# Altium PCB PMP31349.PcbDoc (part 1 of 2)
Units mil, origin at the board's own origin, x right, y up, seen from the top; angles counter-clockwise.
Board outline 2490.35 x 2400.55 mil, 4 copper layers (Top Layer, Internal Layer 1, Internal Layer 2, Bottom Layer), stack 73.068 mil thick; 110 components, 35 nets, 244 pads, 375 vias.
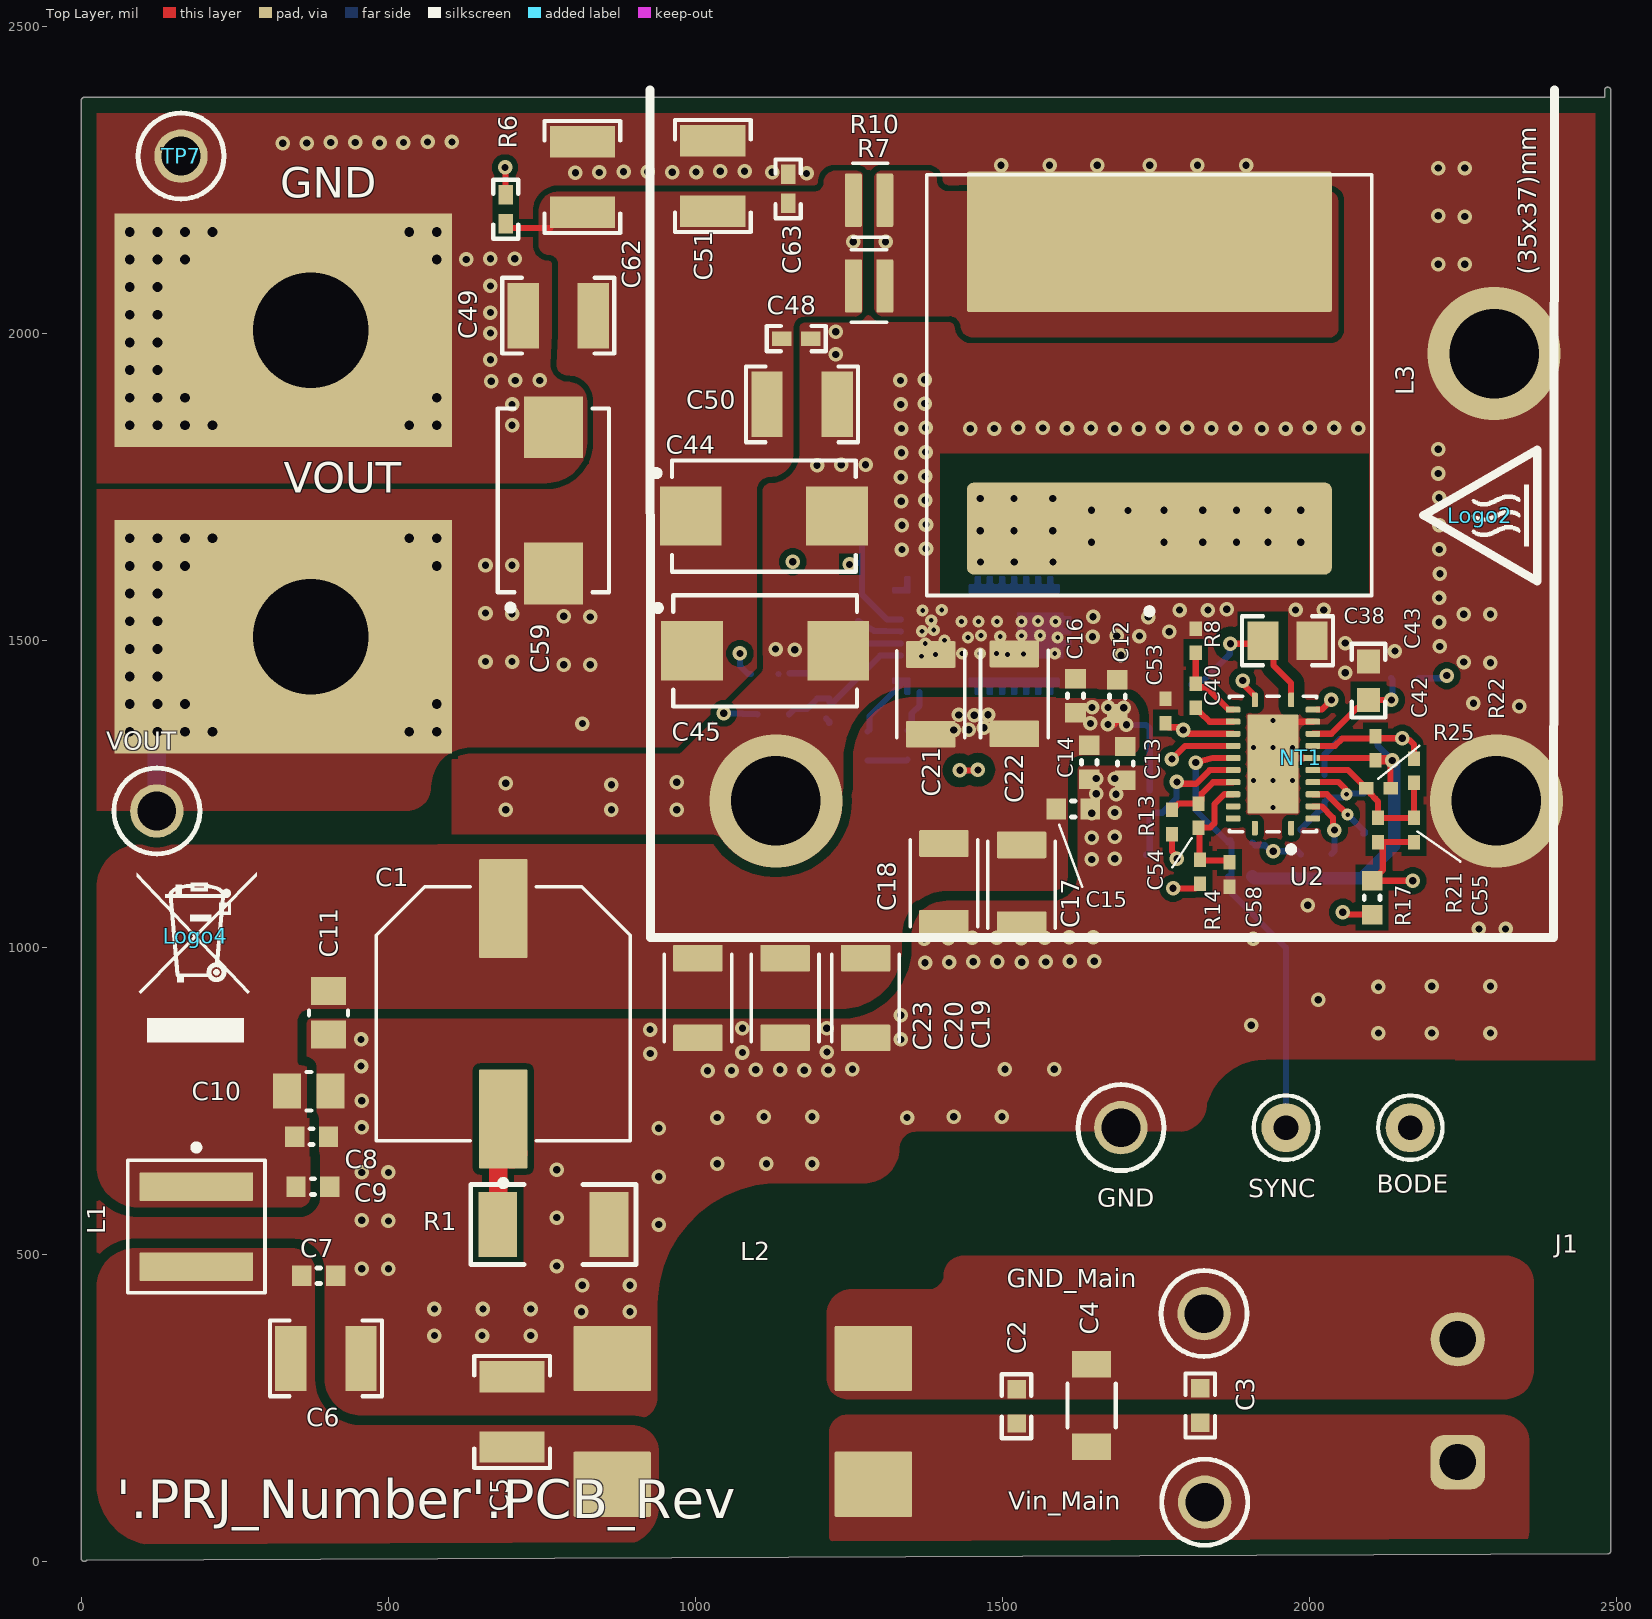
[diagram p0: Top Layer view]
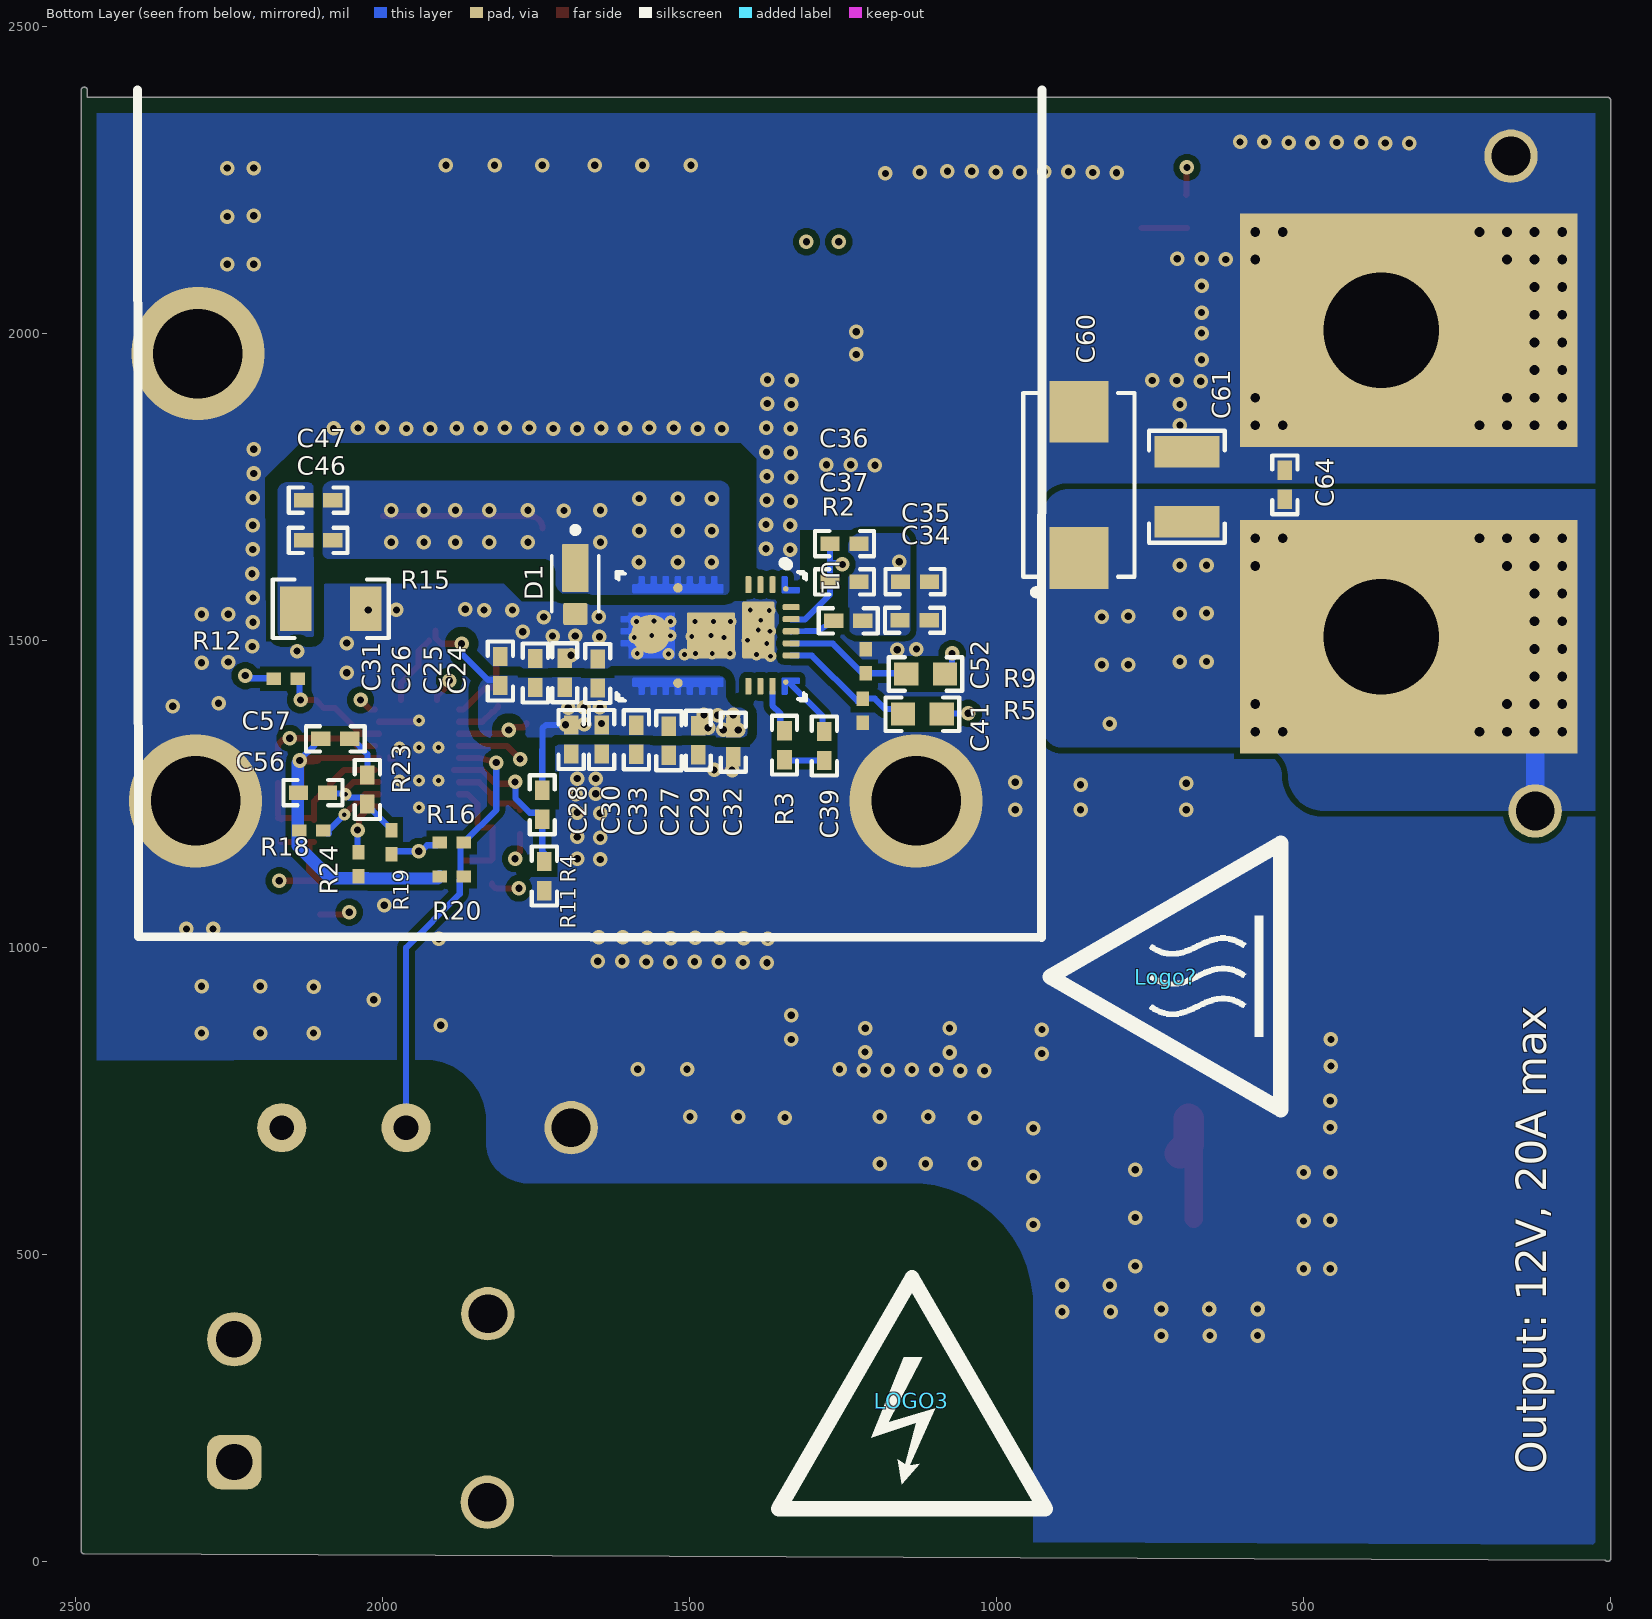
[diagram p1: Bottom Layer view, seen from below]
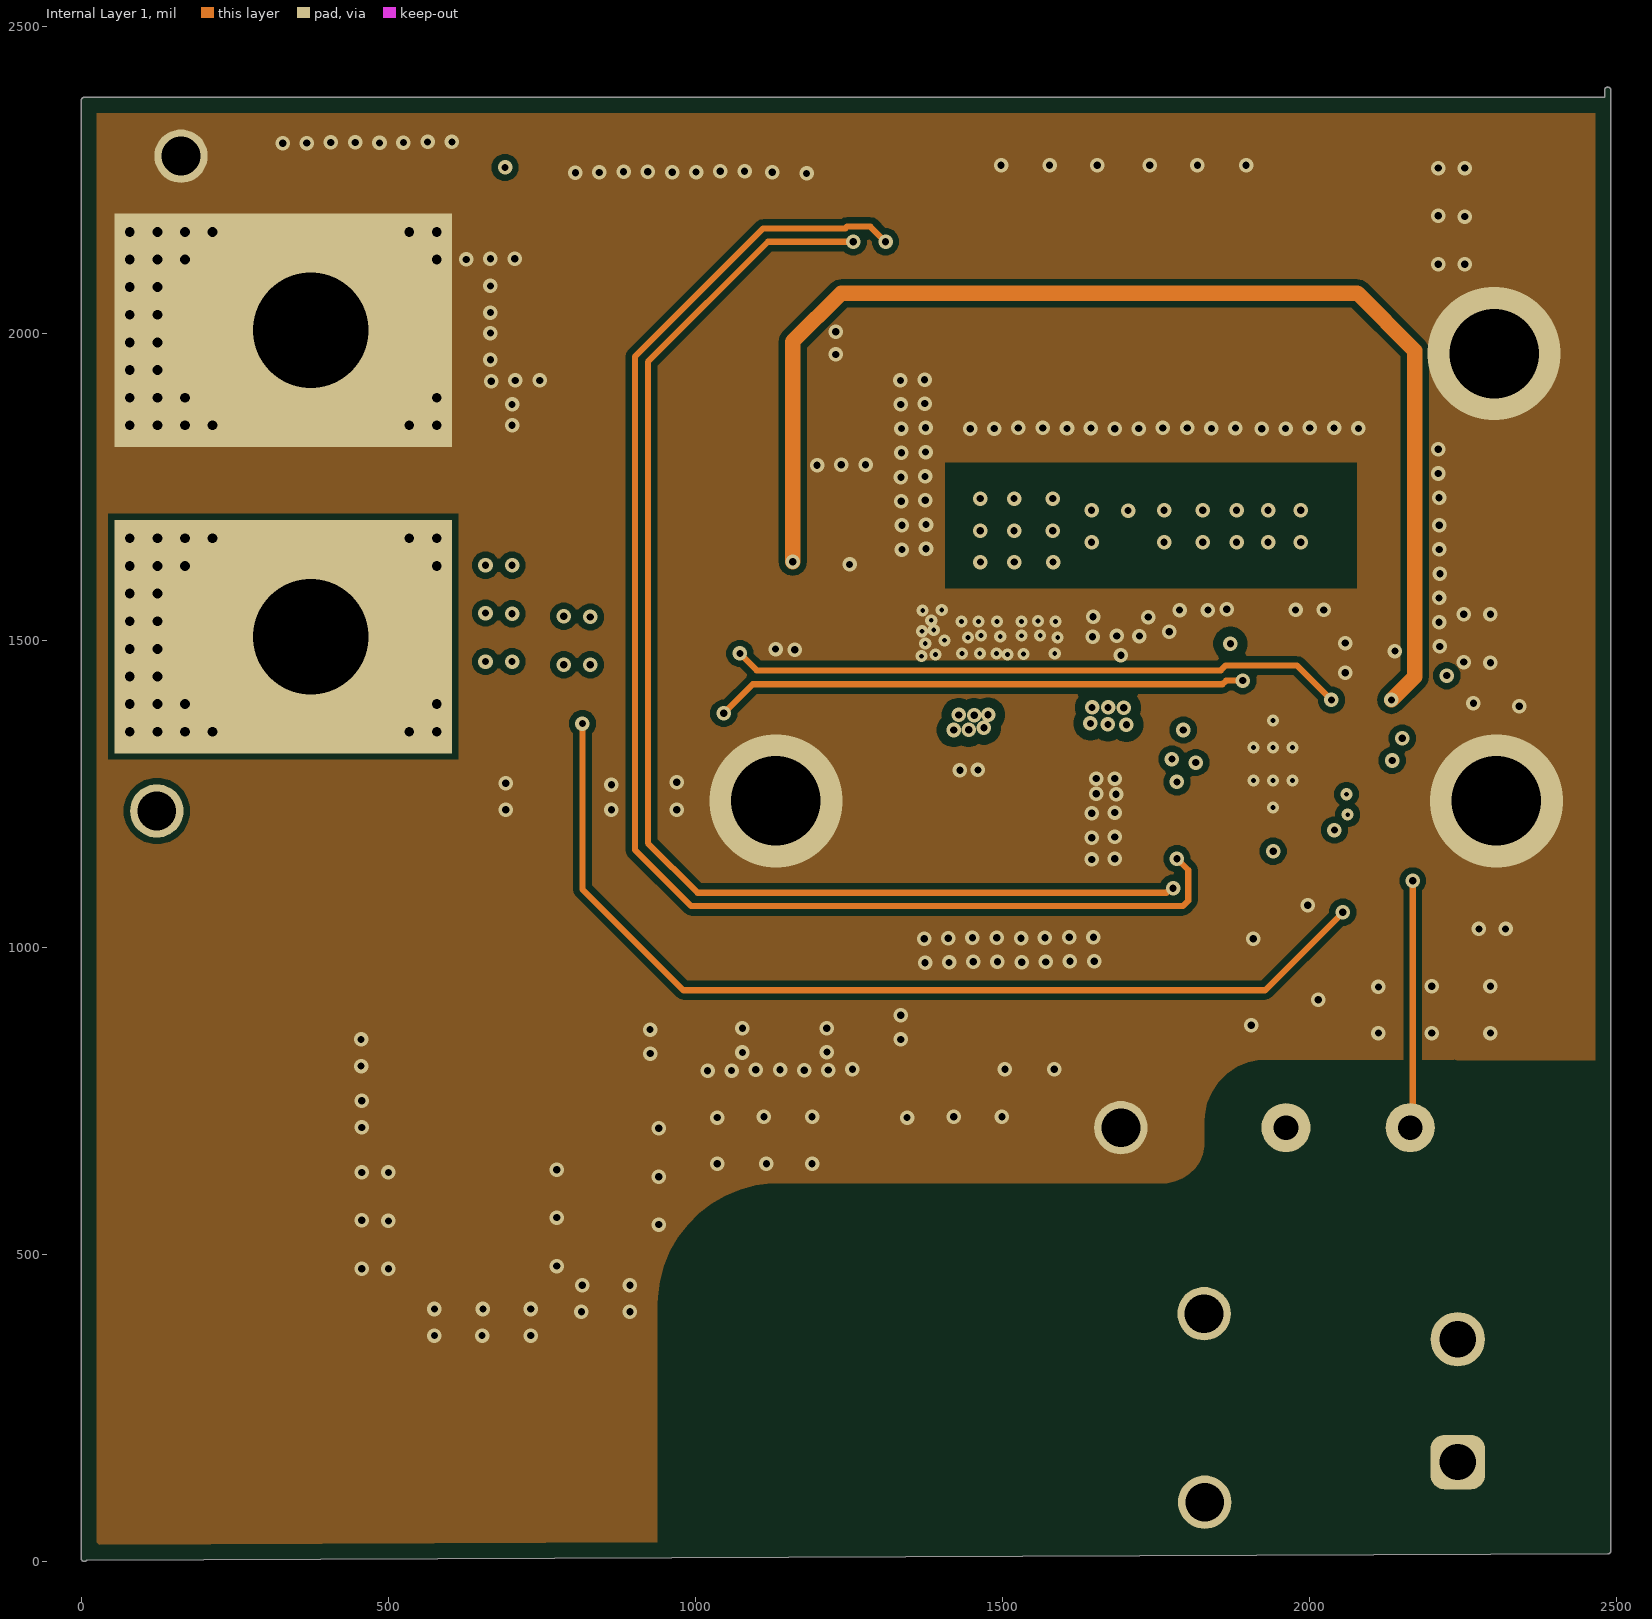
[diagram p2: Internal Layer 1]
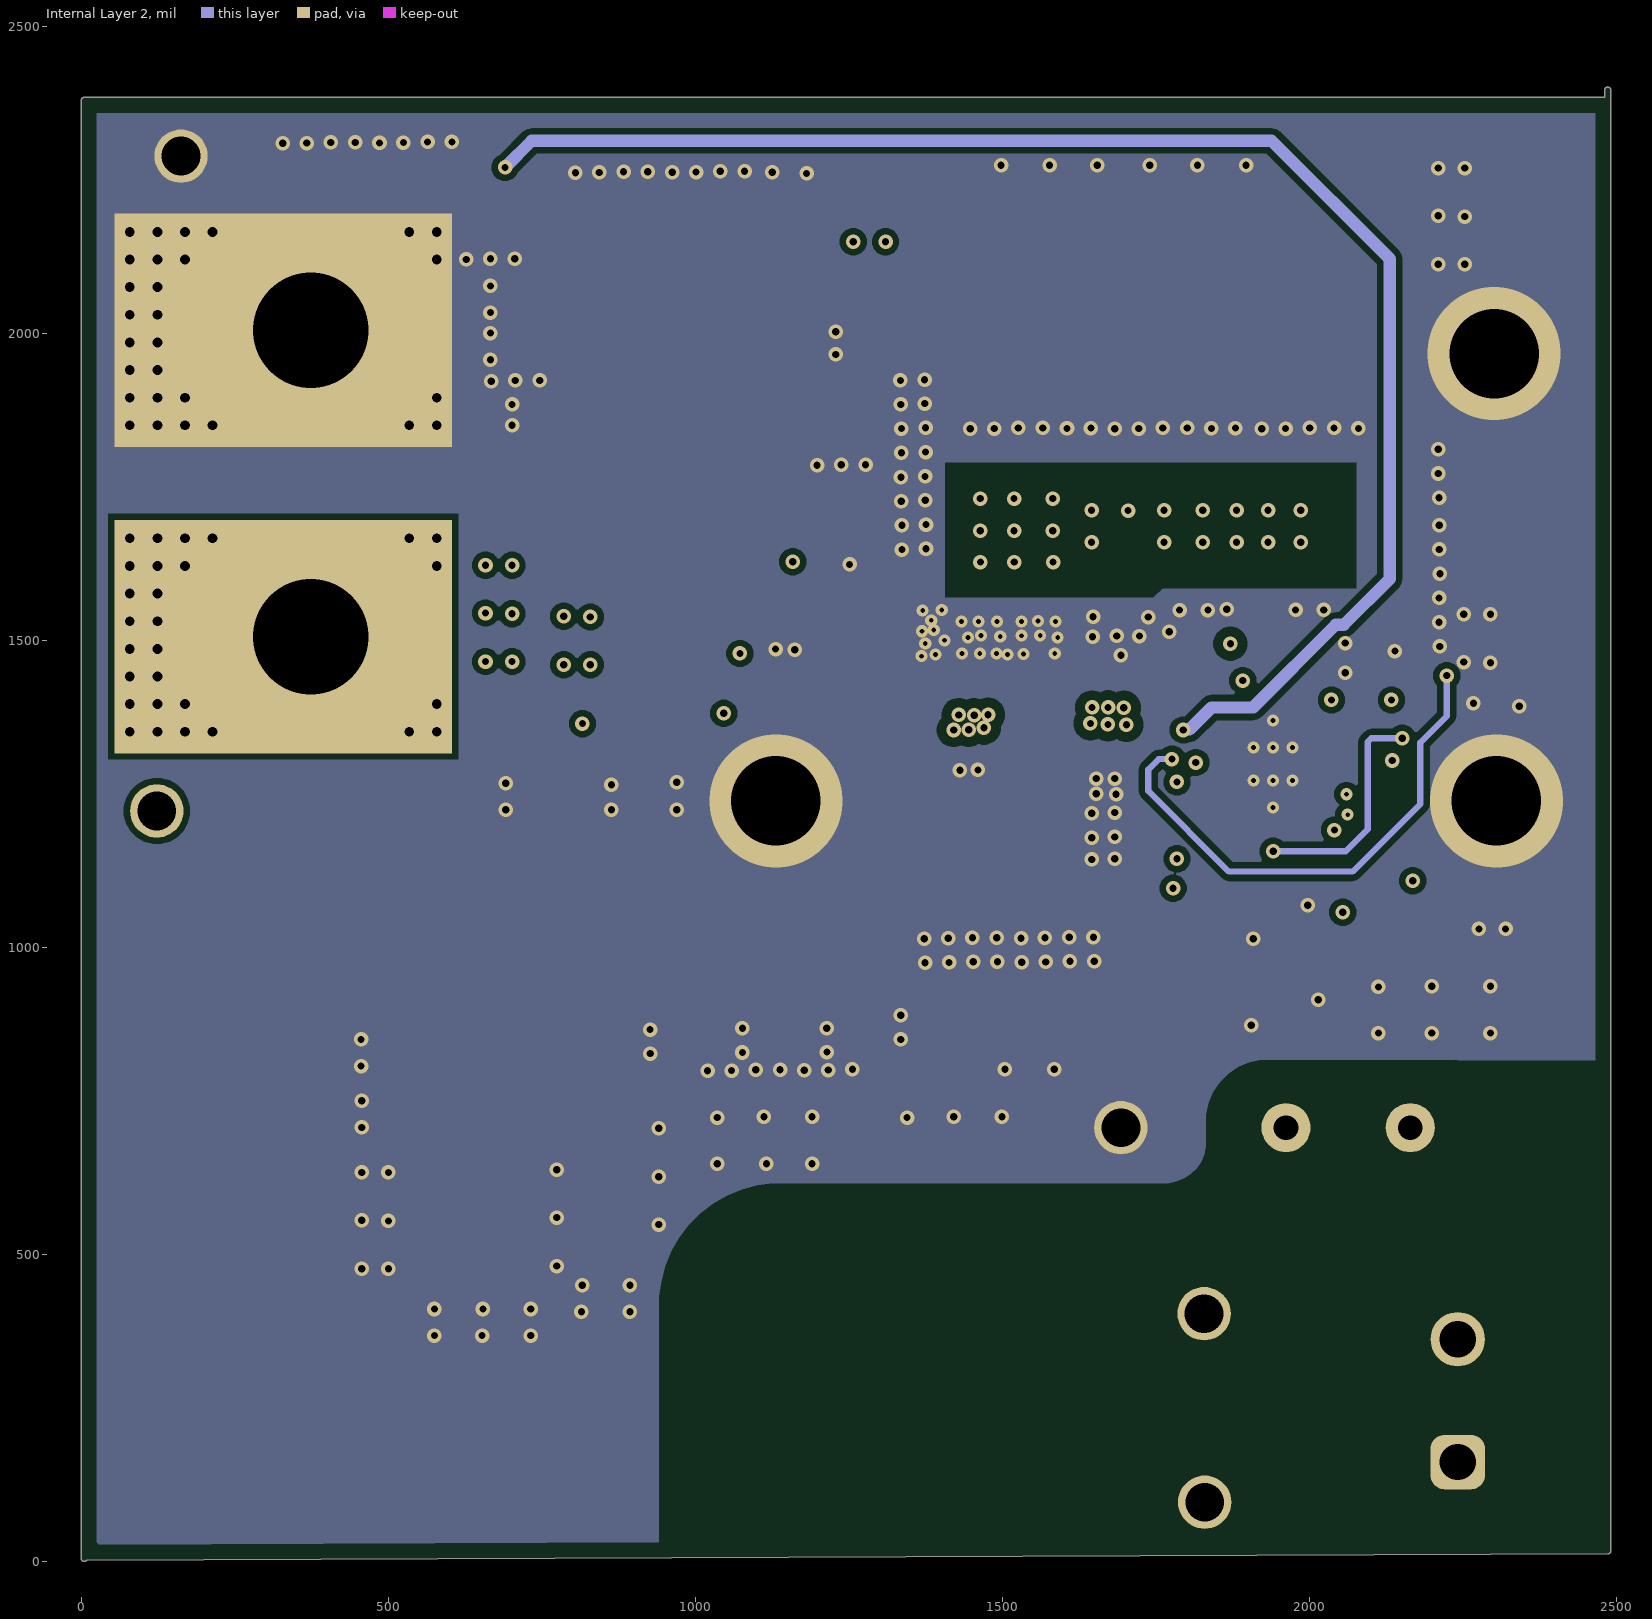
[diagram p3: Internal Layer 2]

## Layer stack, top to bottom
Top Solder: solder mask 0.4, Solder Resist, Dk 3.5
Top Layer: signal copper 2.7559
Dielectric 1: prepreg 2.8, PP-006, Dk 4.1
Internal Layer 1: signal copper 1.378
Dielectric1: dielectric 59.2, FR-4 High Tg, Dk 4.8
Internal Layer 2: signal copper 1.378
Dielectric 2: prepreg 2.8, PP-006, Dk 4.1
Bottom Layer: signal copper 2.7559
Bottom Solder: solder mask 0.4, Solder Resist, Dk 3.5

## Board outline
0.19,5.77 ccw(c5.2,5.77) 9.12,2.64 2485.54,12.95 ccw(c2485.52,17.97) 2490.53,17.97 2490.53,2379.44 2490.53,2396.32 ccw(c2485.52,2396.32) 2480.5,2396.32 2480.5,2384.46 5.2,2384.46 ccw(c5.2,2379.45) 0.19,2379.42

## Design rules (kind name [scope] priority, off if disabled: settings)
AcuteAngle [All] p1: isadvanced=TRUE minimum=4.50000000000000E+0001 checktracksonly=FALSE
AssemblyTestPointUsage [All] p1: isadvanced=TRUE valid=2
AssemblyTestpoint [All] p1: isadvanced=TRUE testpointundercomponent=TRUE minsize=40 maxsize=100 preferedsize=60 minholesize=0 maxholesize=40 preferedholesize=32 testpointgrid=1 usegrid=TRUE gridtolerance=0.01 allowsidetop=TRUE allowsidebottom=TRUE
BoardOutlineClearance BoardOutlineClearance_MountingHoles [OnCopper and InComponentClass('Mounting Holes')] p1: isadvanced=TRUE gap=39.37 ignorepadtopadclearanceinfootprint=FALSE
BoardOutlineClearance BoardOutlineClearance_Poly [OnCopper and IsPoly] p2: isadvanced=TRUE gap=25 ignorepadtopadclearanceinfootprint=FALSE
BoardOutlineClearance [OnCopper and Not InComponentClass('Logo') and not InComponentClass('FiducialMark') and not InRegion(1000,500,4000,800) and not InPoly] p3: isadvanced=TRUE gap=40 ignorepadtopadclearanceinfootprint=FALSE
Clearance Clearance_3 [InNet('+Vin_Main') or InNet('VIN')or InNet('SW') or InNet('+Filter') or InNet('NetC46_2')] p1: isadvanced=TRUE gap=15.75 ignorepadtopadclearanceinfootprint=FALSE
Clearance Clearance_Keepouts [((IsTrack Or IsArc) And Not InPoly) And IsFree and IsKeepOut vs ((IsTrack Or IsArc) And Not InPoly) And IsFree and IsKeepOut] p2: isadvanced=TRUE gap=0 ignorepadtopadclearanceinfootprint=FALSE
Clearance Clearance_Poly [InPolygon] p3: isadvanced=TRUE gap=10 ignorepadtopadclearanceinfootprint=TRUE
Clearance Clearance_FiducialMark [IsKeepOut and InComponentClass('FiducialMark') vs IsPad and InComponentClass('FiducialMark')] p4: isadvanced=TRUE gap=0 ignorepadtopadclearanceinfootprint=FALSE
Clearance Clearance_1 [(ExistsOnLayer('Internal Layer 1') Or ExistsOnLayer('Internal Layer 2')) vs (ExistsOnLayer('Internal Layer 1') Or ExistsOnLayer('Internal Layer 2'))] p5: gap=7.87 ignorepadtopadclearanceinfootprint=TRUE sourcerule=130 cellrowname=All cellrowtype=0 cellcolname=All cellcoltype=0 innerlayers=TRUE
Clearance Clearance_2 [(ExistsOnLayer('Top Layer') Or ExistsOnLayer('Bottom Layer')) vs (ExistsOnLayer('Top Layer') Or ExistsOnLayer('Bottom Layer'))] p6: gap=7.87 ignorepadtopadclearanceinfootprint=TRUE sourcerule=130 cellrowname=All cellrowtype=0 cellcolname=All cellcoltype=0 outerlayers=TRUE
Clearance [All] p7: gap=7.87 ignorepadtopadclearanceinfootprint=TRUE ismatrix=TRUE
ComponentClearance ComponentClearance_1 [(HasFootprint('Net-Tie_10mil'))] p1: isadvanced=TRUE gap=0 collisioncheckmode=3 verticalgap=0 showdistances=FALSE
ComponentClearance ComponentClearance_MountingHoles_FiducialMarks [InComponentClass('Mounting Holes') vs InComponentClass('FiducialMark')] p2: isadvanced=TRUE gap=50 collisioncheckmode=3 verticalgap=10 showdistances=FALSE
ComponentClearance ComponentClearance_Shunt [InComponentClass('Header') vs InComponentClass('Shunt')] p3: isadvanced=TRUE gap=0 collisioncheckmode=3 verticalgap=0 showdistances=FALSE
ComponentClearance ComponentClearance_Logo [InComponentClass('Logo')] p4: isadvanced=TRUE gap=30 collisioncheckmode=3 verticalgap=10 showdistances=FALSE
ComponentClearance ComponentClearance_ScrewToNut [(HasFootprint('NY PMS 440 0025 PH')) vs (HasFootprint('Keystone_1902C'))] p5: isadvanced=TRUE gap=5 collisioncheckmode=3 verticalgap=10 showdistances=FALSE
ComponentClearance ComponentClearance_MountingHoles [InComponentClass('Mounting Holes')] p6: isadvanced=TRUE gap=100 collisioncheckmode=3 verticalgap=100000 showdistances=FALSE
ComponentClearance ComponentClearance_SmallPassives [HasFootprint('0201*') or HasFootprint('0402*') or HasFootprint('0508') or HasFootprint('0603*') or HasFootprint('0612') or HasFootprint('0805*') or HasFootprint('0815*') or HasFootprint('0830*') or HasFootprint('1206*') or HasFootprint('1210*') or HasFootprint('1808*') or HasFootprint('1812*') or HasFootprint('1825*') or HasFootprint('2010*') or HasFootprint('2220*') or HasFootprint('2225*') or HasFootprint('2512*') or HasFootprint('2728*') or HasFootprint('3518*') vs HasFootprint('0201*') or HasFootprint('0402*') or HasFootprint('0508') or HasFootprint('0603*') or HasFootprint('0612') or HasFootprint('0805*') or HasFootprint('0815*') or HasFootprint('0830*') or HasFootprint('1206*') or HasFootprint('1210*') or HasFootprint('1808*') or HasFootprint('1812*') or HasFootprint('1825*') or HasFootprint('2010*') or HasFootprint('2220*') or HasFootprint('2225*') or HasFootprint('2512*') or HasFootprint('2728*') or HasFootprint('3518*')] p7: isadvanced=TRUE gap=14.96 collisioncheckmode=3 verticalgap=10 showdistances=FALSE
ComponentClearance ComponentClearance_THtoSMT [IsThruComponent vs IsSMTComponent] p8: isadvanced=TRUE gap=30 collisioncheckmode=3 verticalgap=30 showdistances=FALSE
ComponentClearance ComponentClearance_THtoTH [IsThruComponent vs IsThruComponent] p9: isadvanced=TRUE gap=20 collisioncheckmode=3 verticalgap=30 showdistances=FALSE
ComponentClearance [All] p10: isadvanced=TRUE gap=20 collisioncheckmode=3 verticalgap=10 showdistances=FALSE
FabricationTestPointUsage TestPointUsage [All] p1: isadvanced=TRUE valid=2 allowmultiple=FALSE
FabricationTestpoint Testpoint [All] p1: isadvanced=TRUE side=3 testpointundercomponent=TRUE minsize=40 maxsize=100 preferedsize=60 minholesize=0 maxholesize=40 preferedholesize=32 testpointgrid=1 allowsidetop=TRUE allowsidebottom=TRUE usegrid=TRUE gridtolerance=0.01
FanoutControl Fanout_LCC [IsLCC] p1: isadvanced=TRUE bgadir=Out bgaviamode=Centered fanoutstyle=Auto fanoutdirection=Alternating viagrid=1 // Fanout_LCC (Default Rule)
FanoutControl Fanout_BGA [IsBGA] p2: isadvanced=TRUE bgadir=Out bgaviamode=Centered fanoutstyle=Auto fanoutdirection=Alternating viagrid=1 // Fanout_BGA (Default Rule)
FanoutControl Fanout_SOIC [IsSOIC] p3: isadvanced=TRUE bgadir=Out bgaviamode=Centered fanoutstyle=Auto fanoutdirection=Alternating viagrid=1 // Fanout_SOIC (Default Rule)
FanoutControl Fanout_Default [All] p4: isadvanced=TRUE bgadir=Out bgaviamode=Centered fanoutstyle=Auto fanoutdirection=Alternating viagrid=1 // Fanout_Default (Default Rule)
FanoutControl Fanout_Small [(CompPinCount < 5)] p5: isadvanced=TRUE bgadir=Out bgaviamode=Centered fanoutstyle=Auto fanoutdirection=OutThenIn viagrid=1 // Fanout_Small (Default Rule)
Height [All] p1: isadvanced=TRUE minheight=0 maxheight=1000 prefheight=500
HoleSize [All] p1: isadvanced=TRUE absolutevalues=TRUE maxlimit=251 minlimit=7.87 maxpercent=80.000 minpercent=20.000
HoleToHoleClearance [All] p1: isadvanced=TRUE gap=10 allowstackedmicrovias=TRUE
LayerPairs [All] p1: isadvanced=TRUE enforce=TRUE
MinimumAnnularRing MinimumAnnularRing_ThermalPadVias [IsVia and InAnyComponent] p1: isadvanced=TRUE minimumring=5.91
MinimumAnnularRing [All] p2: isadvanced=TRUE minimumring=5.91
MinimumSolderMaskSliver MinimumSolderMaskSliver_Logo [InComponentClass('Logo') vs InComponentClass('Logo')] p1: isadvanced=TRUE minsoldermaskwidth=0.7
MinimumSolderMaskSliver [All] p2: isadvanced=TRUE minsoldermaskwidth=3.94
NetAntennae [All] p1: isadvanced=TRUE netantennaetolerance=0
PasteMaskExpansion [All] p1: isadvanced=TRUE expansion=0
PlaneClearance [All] p1: isadvanced=TRUE clearance=20
PlaneConnect [All] p1: isadvanced=TRUE planeconnectstyle=Relief reliefexpansion=10 reliefentries=4 reliefconductorwidth=10 reliefairgap=10
PolygonConnect [All] p1: connectstyle=Direct reliefconductorwidth=10 reliefentries=4 polygonreliefangle="90 Angle" airgapwidth=10
RoutingCorners [All] p1: isadvanced=TRUE cornerstyle=45-Degree minsetback=100 maxsetback=100
RoutingPriority [All] p1: isadvanced=TRUE routingpriority=0
RoutingVias [All] p1: isadvanced=TRUE holewidth=23.62 width=39.37 viastyle="Through Hole" minholewidth=7.87 minwidth=19.68 maxholewidth=31.5 maxwidth=50
RoutingVias RoutingViaStyle_1 [All] p2: holewidth=10 width=10 viastyle="Through Hole" minholewidth=11.81 minwidth=23.62 maxholewidth=11.81 maxwidth=23.62
ShortCircuit [All] p1: isadvanced=TRUE allowed=FALSE
SilkToSilkClearance SilkToSilkClearance_Pb-FreeLogo [(HasFootprint('Pb-Free_Overlay_Medium') OR HasFootprint('Pb-Free_Overlay_Small')) vs (HasFootprint('Pb-Free_Overlay_Medium') OR HasFootprint('Pb-Free_Overlay_Small'))] p1: isadvanced=TRUE silktosilkclearance=0
SilkToSilkClearance [All] p2: isadvanced=TRUE silktosilkclearance=3.94
SilkToSolderMaskClearance SilkToComponentPadClearance [(IsPad or IsFill or IsRegion) and InAnycomponent] p1: isadvanced=TRUE minsilkscreentomaskgap=5 clearancetoexposedcopper=TRUE
SilkToSolderMaskClearance "Silk to Solder Mask Opening" [All] p2: isadvanced=TRUE minsilkscreentomaskgap=3.94 clearancetoexposedcopper=FALSE
SolderMaskExpansion [All] p1: isadvanced=TRUE expansion=1.97 istentingtop=FALSE
SupplyNets "Schematic Supply Nets_70" [InNet('VIN')] p1: voltage=0.000
SupplyNets "Schematic Supply Nets_69" [InNet('VCC')] p2: voltage=0.000
SupplyNets "Schematic Supply Nets_68" [InNet('VDDA')] p3: voltage=0.000
SupplyNets "Schematic Supply Nets_67" [InNet('AGND1')] p4: voltage=0.000
SupplyNets "Schematic Supply Nets_66" [InNet('VOUT')] p5: voltage=0.000
SupplyNets "Schematic Supply Nets_65" [InNet('GND')] p6: voltage=0.000
SupplyNets "Schematic Supply Nets_64" [InNet('VCCX')] p7: voltage=0.000
SupplyNets "Schematic Supply Nets_63" [InNet('FB')] p8: voltage=0.000
SupplyNets "Schematic Supply Nets_62" [InNet('VOUT')] p9: isadvanced=TRUE voltage=0.000
SupplyNets "Schematic Supply Nets_61" [InNet('GND')] p10: isadvanced=TRUE voltage=0.000
SupplyNets "Schematic Supply Nets_60" [InNet('VCC')] p11: isadvanced=TRUE voltage=0.000
SupplyNets "Schematic Supply Nets_59" [InNet('VIN')] p12: isadvanced=TRUE voltage=0.000
SupplyNets "Schematic Supply Nets_58" [InNet('FB')] p13: isadvanced=TRUE voltage=0.000
SupplyNets "Schematic Supply Nets_57" [InNet('VCCX')] p14: isadvanced=TRUE voltage=0.000
SupplyNets "Schematic Supply Nets_56" [InNet('VDDA')] p15: isadvanced=TRUE voltage=0.000
SupplyNets "Schematic Supply Nets_55" [InNet('AGND1')] p16: isadvanced=TRUE voltage=0.000
SupplyNets "Schematic Supply Nets_54" [InNet('AGND1')] p17: isadvanced=TRUE voltage=0.000
SupplyNets "Schematic Supply Nets_53" [InNet('VCCX')] p18: isadvanced=TRUE voltage=0.000
SupplyNets "Schematic Supply Nets_52" [InNet('FB')] p19: isadvanced=TRUE voltage=0.000
SupplyNets "Schematic Supply Nets_51" [InNet('VCC')] p20: isadvanced=TRUE voltage=0.000
SupplyNets "Schematic Supply Nets_50" [InNet('VIN')] p21: isadvanced=TRUE voltage=0.000
SupplyNets "Schematic Supply Nets_49" [InNet('GND')] p22: isadvanced=TRUE voltage=0.000
SupplyNets "Schematic Supply Nets_48" [InNet('VDDA')] p23: isadvanced=TRUE voltage=0.000
SupplyNets "Schematic Supply Nets_47" [InNet('VOUT')] p24: isadvanced=TRUE voltage=0.000
SupplyNets "Schematic Supply Nets_46" [InNet('AGND1')] p25: isadvanced=TRUE voltage=0.000
SupplyNets "Schematic Supply Nets_45" [InNet('GND')] p26: isadvanced=TRUE voltage=0.000
SupplyNets "Schematic Supply Nets_44" [InNet('VCCX')] p27: isadvanced=TRUE voltage=0.000
SupplyNets "Schematic Supply Nets_43" [InNet('VIN')] p28: isadvanced=TRUE voltage=0.000
SupplyNets "Schematic Supply Nets_42" [InNet('VDDA')] p29: isadvanced=TRUE voltage=0.000
SupplyNets "Schematic Supply Nets_41" [InNet('VOUT')] p30: isadvanced=TRUE voltage=0.000
SupplyNets "Schematic Supply Nets_40" [InNet('VCC')] p31: isadvanced=TRUE voltage=0.000
SupplyNets "Schematic Supply Nets_39" [InNet('FB')] p32: isadvanced=TRUE voltage=0.000
SupplyNets "Schematic Supply Nets_38" [InNet('VDDA')] p33: isadvanced=TRUE voltage=0.000
SupplyNets "Schematic Supply Nets_37" [InNet('VCCX')] p34: isadvanced=TRUE voltage=0.000
SupplyNets "Schematic Supply Nets_36" [InNet('FB')] p35: isadvanced=TRUE voltage=0.000
SupplyNets "Schematic Supply Nets_35" [InNet('VOUT')] p36: isadvanced=TRUE voltage=0.000
SupplyNets "Schematic Supply Nets_34" [InNet('VIN')] p37: isadvanced=TRUE voltage=0.000
SupplyNets "Schematic Supply Nets_33" [InNet('GND')] p38: isadvanced=TRUE voltage=0.000
SupplyNets "Schematic Supply Nets_32" [InNet('VCC')] p39: isadvanced=TRUE voltage=0.000
SupplyNets "Schematic Supply Nets_31" [InNet('AGND1')] p40: isadvanced=TRUE voltage=0.000
SupplyNets "Schematic Supply Nets_30" [InNet('AGND1')] p41: isadvanced=TRUE voltage=0.000
SupplyNets "Schematic Supply Nets_29" [InNet('VOUT')] p42: isadvanced=TRUE voltage=0.000
SupplyNets "Schematic Supply Nets_28" [InNet('GND')] p43: isadvanced=TRUE voltage=0.000
SupplyNets "Schematic Supply Nets_27" [InNet('VCC')] p44: isadvanced=TRUE voltage=0.000
SupplyNets "Schematic Supply Nets_26" [InNet('VCCX')] p45: isadvanced=TRUE voltage=0.000
SupplyNets "Schematic Supply Nets_25" [InNet('FB')] p46: isadvanced=TRUE voltage=0.000
SupplyNets "Schematic Supply Nets_24" [InNet('VDDA')] p47: isadvanced=TRUE voltage=0.000
SupplyNets "Schematic Supply Nets_23" [InNet('VIN')] p48: isadvanced=TRUE voltage=0.000
SupplyNets "Schematic Supply Nets_22" [InNet('VDDA')] p49: isadvanced=TRUE voltage=0.000
SupplyNets "Schematic Supply Nets_21" [InNet('VCC')] p50: isadvanced=TRUE voltage=0.000
SupplyNets "Schematic Supply Nets_20" [InNet('VIN')] p51: isadvanced=TRUE voltage=0.000
SupplyNets "Schematic Supply Nets_19" [InNet('GND')] p52: isadvanced=TRUE voltage=0.000
SupplyNets "Schematic Supply Nets_18" [InNet('FB')] p53: isadvanced=TRUE voltage=0.000
SupplyNets "Schematic Supply Nets_17" [InNet('AGND1')] p54: isadvanced=TRUE voltage=0.000
SupplyNets "Schematic Supply Nets_16" [InNet('VCCX')] p55: isadvanced=TRUE voltage=0.000
SupplyNets "Schematic Supply Nets_15" [InNet('VOUT')] p56: isadvanced=TRUE voltage=0.000
SupplyNets "Schematic Supply Nets_14" [InNet('AGND1')] p57: isadvanced=TRUE voltage=0.000
SupplyNets "Schematic Supply Nets_13" [InNet('VCC')] p58: isadvanced=TRUE voltage=0.000
SupplyNets "Schematic Supply Nets_12" [InNet('VOUT')] p59: isadvanced=TRUE voltage=0.000
SupplyNets "Schematic Supply Nets_6" [InNet('FB')] p60: isadvanced=TRUE voltage=0.000
SupplyNets "Schematic Supply Nets_5" [InNet('VCCX')] p61: isadvanced=TRUE voltage=0.000
SupplyNets "Schematic Supply Nets_4" [InNet('VIN')] p62: isadvanced=TRUE voltage=0.000
SupplyNets "Schematic Supply Nets_3" [InNet('GND')] p63: isadvanced=TRUE voltage=0.000
SupplyNets "Schematic Supply Nets_2" [InNet('VDDA')] p64: isadvanced=TRUE voltage=0.000
SupplyNets "Schematic Supply Nets_11" [InNet('VCCX')] p65: isadvanced=TRUE voltage=0.000
SupplyNets "Schematic Supply Nets_10" [InNet('FB')] p66: isadvanced=TRUE voltage=0.000
SupplyNets "Schematic Supply Nets_9" [InNet('VCC')] p67: isadvanced=TRUE voltage=0.000
SupplyNets "Schematic Supply Nets_8" [InNet('AGND1')] p68: isadvanced=TRUE voltage=0.000
SupplyNets "Schematic Supply Nets_7" [InNet('GND')] p69: isadvanced=TRUE voltage=0.000
SupplyNets "Schematic Supply Nets_1" [InNet('VOUT')] p70: isadvanced=TRUE voltage=0.000
SupplyNets "Schematic Supply Nets" [InNet('VIN')] p71: isadvanced=TRUE voltage=0.000
UnRoutedNet [All] p1: isadvanced=TRUE checkbadconnections=TRUE
UnpouredPolygon [All] p1: isadvanced=TRUE
Width [All] p1: maxlimit=50 minlimit=10 preferedwidth=10
4 further rules are at their usual default settings.

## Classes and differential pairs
component class PMP31349_Hardware: Logo2 LOGO3 Logo4 Logo?

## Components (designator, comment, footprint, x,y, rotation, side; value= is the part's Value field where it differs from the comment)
BODE "BODE" Keystone5002 2164.12,706.92 r0 top (schematic designator TP5)
C1 "EEHZA1K470P" FP-EEHZA1K470P_RADIAL_SMT-MFG 687.35,892.38 r90 top value=47µF
C2 "GCM188R72A103KA37J" 0603_HV 1523.08,253.34 r90 top value=0.01uF
C3 "GCM188R72A103KA37J" 0603_HV 1822.15,254.58 r90 top value=0.01uF
C4 "CGA5L3X7S2A225K160AB" 1206_180 1645.13,254.58 r90 top value=2.2uF
C5 "C3225X7S2A475K200AB" 1210_220 701.72,244.08 r270 top value=4.7uF
C6 "CGA6M3X7S2A475K200AB" 1210_220 398.64,331.21 r180 top value=4.7uF
C7 "GCM188R72A103KA37J" 0603L 386.88,465.88 r0 top value=0.01uF
C8 "GCM188R72A103KA37J" 0603L 375.28,692.37 r0 top value=0.01uF
C9 "GCM188R72A103KA37J" 0603L 377.37,610.97 r0 top value=0.01uF
C10 "08051C105K4Z2A" 0805_150 370.71,766.39 r0 top value=1uF
C11 "08051C105K4Z2A" 0805_150 402.84,893.86 r270 top value=1uF
C12 "GCJ188R72A104KA01D" 0603L 1687.24,1408.82 r90 top value=0.1uF
C13 "GCJ188R72A104KA01D" 0603L 1700.23,1299.93 r270 top value=0.1uF
C14 "GCJ188R72A104KA01D" 0603L 1641.46,1301.74 r270 top value=0.1uF
C15 "GCJ188R72A104KA01D" 0603L 1615.2,1225.79 r0 top value=0.1uF
C16 "GCJ188R72A104KA01D" 0603L 1619.03,1410.05 r90 top value=0.1uF
C17 "GCJ32DC72A475KE01L" FP-GCJ32DC72A475KE01L_1210-MFG 1531.22,1102.28 r90 top value=4.7µF
C18 "GCJ32DC72A475KE01L" FP-GCJ32DC72A475KE01L_1210-MFG 1404.85,1104.65 r90 top value=4.7µF
C19 "GCJ32DC72A475KE01L" FP-GCJ32DC72A475KE01L_1210-MFG 1277.23,918.03 r90 top value=4.7µF
C20 "GCJ32DC72A475KE01L" FP-GCJ32DC72A475KE01L_1210-MFG 1146.3,918.03 r90 top value=4.7µF
C21 "" FP-GCJ32DC72A475KE01L_1210-MFG 1383.29,1412.37 r270 top value=4.7µF
C22 "" FP-GCJ32DC72A475KE01L_1210-MFG 1519.41,1413.16 r270 top value=4.7µF
C23 "" FP-GCJ32DC72A475KE01L_1210-MFG 1004.27,918.03 r90 top value=4.7µF
C24 "CGA2B3X7S2A103K050BB" 0402 1649.53,1446.43 r90 bottom value=0.01uF
C25 "CGA2B3X7S2A103K050BB" 0402 1703.31,1447.82 r270 bottom value=0.01uF
C26 "CGA2B3X7S2A103K050BB" 0402 1751.16,1447.17 r270 bottom value=0.01uF
C27 "CGA2B3X7S2A103K050BB" 0402 1533.72,1337.08 r90 bottom value=0.01uF
C28 "CGA2B3X7S2A103K050BB" 0402 1692.99,1338.88 r270 bottom value=0.01uF
C29 "CGA2B3X7S2A103K050BB" 0402 1485.87,1337.74 r90 bottom value=0.01uF
C30 "CGA2B3X7S2A103K050BB" 0402 1643.39,1338.88 r90 bottom value=0.01uF
C31 "CGA2B3X7S2A103K050BB" 0402 1808.07,1450.37 r270 bottom value=0.01uF
C32 "CGA2B3X7S2A103K050BB" 0402 1428.95,1334.53 r90 bottom value=0.01uF
C33 "CGA2B3X7S2A103K050BB" 0402 1586.48,1338.36 r90 bottom value=0.01uF
C34 "C1005X7S1A225K050BC" 0402_065 1133.71,1533.12 r0 bottom value=2.2uF
C35 "C1005X7S1A225K050BC" 0402_065 1132.93,1596.02 r0 bottom value=2.2uF
C36 "GCM155R71C104JA55D" 0402 1247.72,1657.82 r180 bottom value=0.1uF
C37 "GCM155R71C104JA55D" 0402 1247.72,1595.57 r180 bottom value=0.1uF
C38 "08051C474KAT2A" 0805_HV 1964.19,1499.79 r0 top value=0.47uF
C39 "GCM155R71C104JA55D" 0402 1280.57,1328.35 r90 bottom value=0.1uF
C40 "GRM155R71H103KA88D" 0402L 1814.77,1410.05 r90 top value=0.01uF
C41 "GRM1555C1H100FA01D" 0402L 1218.12,1385.78 r90 bottom value=10pF
C42 "C0402C104K8RACAUTO" 0402L 2107.23,1324.67 r90 top value=0.1uF
C43 "C1608X7S1A475K080AC" 0603 2096.08,1434.62 r90 top value=4.7uF
C44 "T598D157M016ATE065" 7343-31 1111.72,1702.71 r0 top value=150uF
C45 "T598D157M016ATE065" 7343-31 1113.65,1483.26 r0 top value=150uF
C46 "C1005C0G2A331J050BE" 0402 2104.88,1663.07 r0 bottom value=330pF
C47 "C1005C0G2A331J050BE" 0402 2104.88,1728.81 r0 bottom value=330pF
C48 "CGA2B3X7R1E104K050BB" 0402 1164.33,1991.56 r0 top value=0.1uF
C49 "DNP" 1210_270 776.86,2029.03 r180 top value=22uF
C50 "TMK325B7226KMHP" 1210_270 1173.81,1884.57 r0 top value=22uF
C51 "TMK325B7226KMHP" 1210_270 1028.55,2256.37 r90 top value=22uF
C52 "GRM1555C1H100FA01D" 0402L 1213.28,1466.41 r90 bottom value=10pF
C53 "CGA2B3X7R1E104K050BB" 0402L 1765.71,1385.48 r90 top value=0.1uF
C54 "CGA2B1X7R1E333K050BC" 0402L 1819.61,1215.02 r90 top value=0.033uF
C55 "GRM1555C1H100FA01D" 0402L 2169.86,1191.48 r90 top value=10pF
C56 "GCM1555C1H681FA16D" 0402 2113.26,1252.58 r0 bottom value=680pF
C57 "GRM155R71E562KA01D" 0402 2076.69,1339.85 r0 bottom value=5600pF
C58 "GRM155R72A271KA01D" 0402L 1869.6,1119.12 r90 top value=270pF
C59 "DNP" 7343-31 769.02,1728.36 r90 top value=150uF
C60 "DNP" 7343-31 866.17,1753.47 r90 bottom value=150uF
C61 "DNP" 1210_270 690.24,1750.24 r90 bottom value=22uF
C62 "TMK325B7226KMHP" 1210_270 816.23,2254.82 r90 top value=22uF
C63 "CGA2B3X7R1E104K050BB" 0402 1151.07,2235.42 r90 top value=0.1uF
C64 "CGA2B3X7R1E104K050BB" 0402 530.88,1753.47 r90 bottom value=0.1uF
D1 "PMEG100T20ELXD-Q" FP-SS16HE_SOD-323HE-MFG 1686.06,1592.52 r270 bottom
GND "GND" Keystone5011 1692.99,706.92 r0 top (schematic designator TP6)
GND "GND" CB35-36-CY 374.15,2005.46 r0 top (schematic designator T2)
GND_Main "GND_IN" Keystone5011 1828.4,404.19 r0 top (schematic designator TP2)
J1 "691236510002" Wurth_691236510002 2241.43,262.46 r90 top
L1 "XGL5050-122MEC" FP-XGL5050-122MEC_SMT_IND_5MM28_5MM48-MFG 187.6,545.82 r270 top value=1.2uH
L2 "" TDK_ACM12V 1077.34,228.75 r180 top
L3 "XGL1712-332MED" FP-XGL1712-332MED_SMT2_17MM2_18MM2-MFG 1739.29,1915.83 r90 top value=3.3uH
Logo2 "CAUTION HOT SURFACE" IEC_HotSurface_Small 2278,1703.89 r90 top
LOGO3 "DANGER HIGH VOLTAGE" IEC_HighVoltage_Medium 1137.93,262.09 r180 bottom
Logo4 "WEEE logo" WEEE_Minimum 186.31,1018.36 r0 top
Logo? "CAUTION HOT SURFACE" IEC_HotSurface_Medium 724.75,952.88 r90 bottom (schematic designator Logo1)
NT1 "Net-Tie" Net-Tie_10mil 1985.63,1308.89 r0 top net-tie
R1 "CRM2010-JW-1R0ELF" 2010 769.02,549.21 r180 top value=1.0
R2 "CRCW04020000Z0ED" 0402 1241.65,1532.09 r180 bottom value=0
R3 "CRCW04020000Z0ED" 0402 1345.5,1329.8 r90 bottom value=0
R4 "CRCW0402499KFKED" 0402 1739.82,1232.52 r90 bottom value=499k
R5 "RC0603JR-070RL" 0603 1121.07,1380.15 r0 bottom value=0
R6 "CRCW04020000Z0ED" 0402 691.37,2202.37 r90 top value=0
R7 "KRL2012E-M-R003-F-T5" FP-KRL2012E-M-R003-F-T5_0805-MFG 1282.93,2077.42 r180 top value=3m
R8 "CRCW04020000Z0ED" 0402L 1814.77,1499.79 r90 top value=0
R9 "RC0603JR-070RL" 0603 1115.85,1445.44 r0 bottom value=0
R10 "KRL2012E-M-R004-F-T5" FP-KRL2012E-M-R004-F-T5_2012-MFG 1282.93,2217 r180 top value=4m
R11 "CRCW040219K1FKED" 0402 1736.56,1116.57 r90 bottom value=19.1k
R12 "DNP" 0402L 2157.44,1437.78 r180 bottom value=100k
R13 "CRCW040249R9FKED" 0402L 1776.11,1204.61 r270 top value=49.9
R14 "CRCW04020000Z0ED" 0402L 1821.87,1123.79 r270 top value=0
R15 "CRCW120647R0JNEA" 1206 2084.39,1551.77 r0 bottom value=47
R16 "DNP" 0402L 1887.02,1171.5 r180 bottom value=0
R17 "CRCW060349R9FKEA" 0603L 2101.9,1081.35 r270 top value=49.9
R18 "CRCW040273K2FKED" 0402L 2115.94,1190.72 r0 bottom value=73.2k
R19 "DNP" 0402L 1985.68,1171.5 r270 bottom value=100k
R20 "" 0402L 1887.02,1116.12 r0 bottom value=0
R21 "RMCF0402FT100K" 0402L 2111.71,1191.48 r270 top value=100k
R22 "CRCW040249K9FKED" 0402L 2170.43,1288.14 r90 top value=49.9k
R23 "CRCW040210K2FKED" 0402 2024.54,1257.44 r270 bottom value=10.2k
R24 "CRCW040229K4FKED" 0402L 2039.07,1135.96 r270 bottom value=29.4k
R25 "CRCW04027K15FKED" 0402L 2112.23,1259.62 r180 top value=7.15k
SYNC "SYNCIN" Keystone5002 1961.71,706.92 r0 top (schematic designator TP4)
TP7 "GND" Keystone5011 162.69,2288.82 r0 top
U1 "LMG2100R026" VBN0016A-MFG 1466.46,1508.31 r270 bottom
U2 "LM5148QRGYRQ1" RGY0024E-MFG 1940.57,1298.99 r180 top
Vin_Main "VIN" Keystone5010 1829.44,97.1 r0 top (schematic designator TP1)
VOUT "VOUT" Keystone5010 123.32,1222.56 r0 top (schematic designator TP3)
VOUT "VOUT" CB35-36-CY 374.15,1506.55 r0 top (schematic designator T1)

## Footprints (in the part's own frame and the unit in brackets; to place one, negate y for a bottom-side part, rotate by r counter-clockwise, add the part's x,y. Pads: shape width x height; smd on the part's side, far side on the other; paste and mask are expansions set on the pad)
0402 [mm] "0402 from SM-752 data"
  rect 0.8x0.6 smd: 1(-0.6,0) 2(0.6,0)
  silkscreen extent -1.22,-0.52 1.22,0.52, body extent -0.55,-0.3 0.55,0.3, height 0.6
0402_065 [mm] "0402"
  rect 0.8x0.6 smd: 1(-0.6,0) 2(0.6,0)
  silkscreen extent -1.22,-0.52 1.22,0.52, body extent -0.55,-0.3 0.55,0.3, height 0.65
0402L [mm] "0402 from SM-752 data"
  rect 0.6x0.5 smd: 1(-0.5,0) 2(0.5,0)
  body extent -0.55,-0.3 0.55,0.3, height 0.6
0603 [mm] "0603 from SM-752 data"
  rect 1x0.95 smd: 1(-0.8,0) 2(0.8,0)
  silkscreen extent -1.52,-0.69 1.52,0.69, body extent -0.87,-0.47 0.87,0.47, height 1
0603_HV [mil] "Ernesto recommended land pattern.  26 mil between pads."
  rect 30x30 smd: 1(-28,0) 2(28,0)
  silkscreen extent -52,-24 52,24, body extent -34,-19 34,19, height 39
0603L [mm] "0603 from SM-752 data"
  rect 0.8x0.85 smd: 1(-0.7,0) 2(0.7,0)
  silkscreen extent -0.07,-0.33 0.07,0.33, body extent -0.87,-0.47 0.87,0.47, height 1
0805_150 [mm] "0805 / 1.5 mm height"
  rect 1.15x1.45 smd: 1(-0.9,0) 2(0.9,0)
  silkscreen extent -0.1,-0.8 0.1,0.8, body extent -1.1,-0.72 1.1,0.72, height 1.5
0805_HV [mil] "0805 with 30mil clearance between pads"
  rect 50x63 smd: 1(-40,0) 2(40,0)
  silkscreen extent -74,-40 74,40, body extent -43,-29 43,29, height 57
1206 [mm] "1206 from SM-752 data"
  rect 1.3x1.85 smd: 1(-1.45,0) 2(1.45,0)
  silkscreen extent -2.4,-1.21 2.4,1.21, body extent -1.7,-0.9 1.7,0.9, height 1.35
1206_180 [mm] "1206_180"
  rect 1.1x1.6 smd: 1(-1.7,0) 2(1.7,0)
  silkscreen extent -0.9,-1 0.9,1, body extent -1.75,-0.95 1.75,0.95, height 1.8
1210_220 [mm] "1210"
  rect 1.3x2.7 smd: 1(-1.45,0) 2(1.45,0)
  silkscreen extent -2.32,-1.57 2.32,1.57, body extent -1.7,-1.35 1.7,1.35, height 2.2
1210_270 [mm] "1210"
  rect 1.3x2.7 smd: 1(-1.45,0) 2(1.45,0)
  silkscreen extent -2.32,-1.57 2.32,1.57, body extent -1.7,-1.35 1.7,1.35, height 2.7
2010 [mm] "Chip Capacitor, Body 5.08x2.54mm, IPC Medium Density"
  rect 1.6x2.7 smd: 1(-2.3,0) 2(2.3,0)
  silkscreen extent -3.42,-1.65 3.42,1.65, body extent -2.73,-1.45 2.73,1.45, height 1.66
7343-31 [mm] "Medium Density based on Kemet T495 dimensions"
  rect 2.55x2.45 smd: 1(-3.025,0) 2(3.025,0)
  silkscreen extent -4.56,-2.3 3.8,2.3, body extent -3.8,-2.3 3.8,2.3, height 3.1
CB35-36-CY [mil] "Terminal 50A Lug"
  rect 550x380 hole 188 copper offset -45,0 paste-99999: 1(0,0)
  body extent -960,-189 230,191, height 614
FP-EEHZA1K470P_RADIAL_SMT-MFG [mm]
  rrect5% 4.1x2 smd paste+0 mask+0: 1(-4.35,0) 2(4.35,0)
  silkscreen extent -7.12,-5.25 5.25,5.25, body extent -6.65,-5.5 6.65,5.5, height 0.25
FP-GCJ32DC72A475KE01L_1210-MFG [mm]
  rrect9% 1.1x2.05 smd paste+0 mask+0: 1(-1.65,0) 2(1.65,0)
  silkscreen extent -1.8,-1.4 1.8,1.4, body extent -1.6,-1.25 1.6,1.25, height 2.3
FP-KRL2012E-M-R003-F-T5_0805-MFG [mm]
  rrect14% 0.7x2.2 smd paste+0 mask+0: 1(-0.65,0) 2(0.65,0)
  silkscreen extent -0.72,-1.5 0.72,1.5, body extent -0.63,-1 0.63,1, height 0.7
FP-KRL2012E-M-R004-F-T5_2012-MFG [mm]
  rrect14% 0.7x2.2 smd paste+0 mask+0: 1(-0.65,0) 2(0.65,0)
  silkscreen extent -0.77,-1.53 0.67,1.53, body extent -0.63,-1 0.63,1, height 0.7
FP-SS16HE_SOD-323HE-MFG [mm]
  rrect9% 2x1.1 smd paste+0 mask+0: 1(-0.65,0)
  rrect13% 0.9x1 smd paste+0 mask+0: 2(1.25,0)
  silkscreen extent -2.35,-0.97 1.15,0.97, body extent -1.25,-0.64 1.25,0.64, height 0.75
FP-XGL1712-332MED_SMT2_17MM2_18MM2-MFG [mm]
  rrect15% 3.8x15.1 smd paste+0 mask+0: 1(-5.93,0)
  rrect3% 5.8x15.1 smd paste+0 mask+0: 2(5.93,0)
  silkscreen extent -9.47,-9.2 8.7,9.2, body extent -8.6,-9.1 8.6,9.1, height 12
FP-XGL5050-122MEC_SMT_IND_5MM28_5MM48-MFG [mm]
  rrect8% 1.18x4.7 smd paste+0 mask+0: 1(-1.655,0) 2(1.655,0)
  silkscreen extent -3.4,-2.84 2.74,2.84, body extent -2.84,-2.94 2.84,2.94, height 0.25
IEC_HighVoltage_Medium [mil]
  silkscreen extent -217,-176 217,200
IEC_HotSurface_Medium [mil]
  silkscreen extent -217,-188 217,188
IEC_HotSurface_Small [mil]
  silkscreen extent -107,-93 107,92
Keystone5002 [mil] "For Keystone 500x miniature loop terminals"
  round 80 hole 40: 1(0,0)
  silkscreen extent -52,-52 52,52, body extent -49,-49 49,49, height 182
Keystone5010 [mil] "Keystone Multipurpose loops"
  round 87 hole 63: 1(0,0)
  silkscreen extent -70,-70 70,70, body extent -63,-63 63,62, height 319
Keystone5011 [mil] "Keystone Multipurpose loops"
  round 87 hole 63: 1(0,0)
  silkscreen extent -70,-70 70,70, body extent -63,-63 63,62, height 319
Net-Tie_10mil [mil] "10mil net tie, no solder mask opening, no solder paste"
  rect 10x10 smd paste-5 mask-5: 1(-10,0) 2(10,0)
  Top Layer region: -6,5 6,5 6,-5 -6,-5
RGY0024E-MFG [mm]
  rrect40% 0.25x0.6 smd paste+0 mask+0: 1(-0.75,2.65) 12(-0.75,-2.65) 13(0.75,-2.65) 24(0.75,2.65)
  rrect40% 0.6x0.25 smd paste+0 mask+0: 2(-1.65,2.25) 3(-1.65,1.75) 4(-1.65,1.25) 5(-1.65,0.75) 6(-1.65,0.25) 7(-1.65,-0.25) 8(-1.65,-0.75) 9(-1.65,-1.25) 10(-1.65,-1.75) 11(-1.65,-2.25) 14(1.65,-2.25) 15(1.65,-1.75) 16(1.65,-1.25) 17(1.65,-0.75) 18(1.65,-0.25) 19(1.65,0.25) 20(1.65,0.75) 21(1.65,1.25) 22(1.65,1.75) 23(1.65,2.25)
  rrect5% 2.1x4.1 smd paste-1000 mask+0: 25(0,0)
  silkscreen extent -1.8,-2.8 1.8,3.65, body extent -2.05,-3.05 2.05,3.05, height 0.25
TDK_ACM12V [mm] "SMD, 4-Leads, Body 12x11mm, Pitch 5.2mm"
  rrect4% 3.2x2.7 smd: 1(-5.4,2.6) 2(-5.4,-2.6) 3(5.4,-2.6) 4(5.4,2.6)
  body extent -6,-5.5 6,5.5, height 5.55
VBN0016A-MFG [mm]
  round 0.228 smd paste+0 mask+0: 1(-1.925,3.125) 11(1.925,3.125)
  rrect40% 0.7x0.25 smd paste+0 mask+0: 2(-2.1,2.575) 3(-2.1,2.075) 4(-2.1,1.575) 8(2.1,1.575) 9(2.1,2.075) 10(2.1,2.575)
  round 0.394 smd paste+0 mask+0: 5(-1.969,-1.335) 7(1.969,-1.335)
  rrect8% 2.35x1.33 smd paste-1000 mask+0: 6(-0.225,1.985)
  round 1.603 smd paste-1000 mask+0: 6(-0.059,-2.453)
  rrect5% 1.9x1.976 smd paste-1000 mask+0: 6(0,0.032)
  rrect40% 0.25x0.7 smd paste+0 mask+0: 12(0.825,3.35) 13(0.325,3.35) 14(-0.175,3.35) 15(-0.675,3.35) 16(-1.175,3.35)
  Top Layer region: -2.4,2.95 -2.419,2.954 -2.435,2.965 -2.446,2.981 -2.45,3 -2.45,3 -2.45,3.15 -2.443,3.175 -2.425,3.193 -2.4,3.2 -2.4,3.2 -2.05,3.2 -2.031,3.204 -2.015,3.215 -2.004,3.231 -2,3.25 -2,3.25 -2,3.65 -1.993,3.675 -1.975,3.693 -1.95,3.7 -1.95,3.7 -1.8,3.7 -1.781,3.696 -1.765,3.685 -1.754,3.669 -1.75,3.65 -1.75,3.65 -1.75,3 -1.754,2.981 -1.765,2.965 -1.781,2.954 -1.8,2.95 -1.8,2.95
  Top Layer region: 2.4,2.95 2.419,2.954 2.435,2.965 2.446,2.981 2.45,3 2.45,3 2.45,3.15 2.446,3.169 2.435,3.185 2.419,3.196 2.4,3.2 2.4,3.2 2.05,3.2 2.025,3.207 2.007,3.225 2,3.25 2,3.25 2,3.65 1.996,3.669 1.985,3.685 1.969,3.696 1.95,3.7 1.95,3.7 1.8,3.7 1.781,3.696 1.765,3.685 1.754,3.669 1.75,3.65 1.75,3.65 1.75,3 1.754,2.981 1.765,2.965 1.781,2.954 1.8,2.95 1.8,2.95
  Top Layer region: -0.55,-3.65 -0.554,-3.669 -0.565,-3.685 -0.581,-3.696 -0.6,-3.7 -0.6,-3.7 -0.75,-3.7 -0.775,-3.693 -0.793,-3.675 -0.8,-3.65 -0.8,-3.65 -0.8,-3.425 -0.804,-3.406 -0.815,-3.39 -0.831,-3.379 -0.85,-3.375 -0.85,-3.375 -0.9,-3.375 -0.925,-3.368 -0.943,-3.35 -0.95,-3.325 -0.95,-3.325 -0.95,-1.506 -0.943,-1.481 -0.925,-1.463 -0.9,-1.456 -0.9,-1.456 0.9,-1.456 0.919,-1.46 0.935,-1.471 0.946,-1.487 0.95,-1.506 0.95,-1.506 0.95,-3.325 0.943,-3.35 0.925,-3.368 0.9,-3.375 0.9,-3.375 0.5,-3.375 0.481,-3.379 0.465,-3.39 0.454,-3.406 0.45,-3.425 0.45,-3.425 0.45,-3.65 0.443,-3.675 0.425,-3.693 0.4,-3.7 0.4,-3.7 0.25,-3.7 0.231,-3.696 0.215,-3.685 0.204,-3.669 0.2,-3.65 0.2,-3.65 0.2,-3.425 0.196,-3.406 0.185,-3.39 0.169,-3.379 0.15,-3.375 0.15,-3.375 0,-3.375 -0.019,-3.379 -0.035,-3.39 -0.046,-3.406 -0.05,-3.425 -0.05,-3.425 -0.05,-3.65 -0.054,-3.669 -0.065,-3.685 -0.081,-3.696 -0.1,-3.7 -0.1,-3.7 -0.25,-3.7 -0.275,-3.693 -0.293,-3.675 -0.3,-3.65 -0.3,-3.65 -0.3,-3.425 -0.304,-3.406 -0.315,-3.39 -0.331,-3.379 -0.35,-3.375 -0.35,-3.375 -0.5,-3.375 -0.519,-3.379 -0.535,-3.39 -0.546,-3.406 -0.55,-3.425 -0.55,-3.425
  Top Layer region: -2.075,0.542 -2.1,0.535 -2.118,0.517 -2.125,0.492 -2.125,0.492 -2.125,0.338 -2.129,0.319 -2.14,0.303 -2.156,0.292 -2.175,0.288 -2.175,0.288 -2.4,0.288 -2.425,0.281 -2.443,0.263 -2.45,0.238 -2.45,0.238 -2.45,0.088 -2.443,0.063 -2.425,0.045 -2.4,0.038 -2.4,0.038 -2.175,0.038 -2.15,0.031 -2.132,0.013 -2.125,-0.012 -2.125,-0.012 -2.125,-0.162 -2.132,-0.187 -2.15,-0.205 -2.175,-0.212 -2.175,-0.212 -2.4,-0.212 -2.419,-0.216 -2.435,-0.227 -2.446,-0.243 -2.45,-0.262 -2.45,-0.262 -2.45,-0.412 -2.443,-0.437 -2.425,-0.455 -2.4,-0.462 -2.4,-0.462 -2.175,-0.462 -2.156,-0.466 -2.14,-0.477 -2.129,-0.493 -2.125,-0.512 -2.125,-0.512 -2.125,-0.662 -2.129,-0.681 -2.14,-0.697 -2.156,-0.708 -2.175,-0.712 -2.175,-0.712 -2.4,-0.712 -2.419,-0.716 -2.435,-0.727 -2.446,-0.743 -2.45,-0.762 -2.45,-0.762 -2.45,-0.912 -2.443,-0.937 -2.425,-0.955 -2.4,-0.962 -2.4,-0.962 -2.175,-0.962 -2.156,-0.966 -2.14,-0.977 -2.129,-0.993 -2.125,-1.012 -2.125,-1.012 -2.125,-1.162 -2.129,-1.181 -2.14,-1.197 -2.156,-1.208 -2.175,-1.212 -2.175,-1.212 -2.4,-1.212 -2.419,-1.216 -2.435,-1.227 -2.446,-1.243 -2.45,-1.262 -2.45,-1.262 -2.45,-1.412 -2.443,-1.437 -2.425,-1.455 -2.4,-1.462 -2.4,-1.462 -2.175,-1.462 -2.156,-1.466 -2.14,-1.477 -2.129,-1.493 -2.125,-1.512 -2.125,-1.512 -2.125,-1.662 -2.129,-1.681 -2.14,-1.697 -2.156,-1.708 -2.175,-1.712 -2.175,-1.712 -2.4,-1.712 -2.419,-1.716 -2.435,-1.727 -2.446,-1.743 -2.45,-1.762 -2.45,-1.762 -2.45,-1.912 -2.443,-1.937 -2.425,-1.955 -2.4,-1.962 -2.4,-1.962 -2.175,-1.962 -2.156,-1.966 -2.14,-1.977 -2.129,-1.993 -2.125,-2.012 -2.125,-2.012 -2.125,-2.162 -2.129,-2.181 -2.14,-2.197 -2.156,-2.208 -2.175,-2.212 -2.175,-2.212 -2.4,-2.212 -2.419,-2.216 -2.435,-2.227 -2.446,-2.243 -2.45,-2.262 -2.45,-2.262 -2.45,-2.412 -2.443,-2.437 -2.425,-2.455 -2.4,-2.462 -2.4,-2.462 -2.175,-2.462 -2.156,-2.466 -2.14,-2.477 -2.129,-2.493 -2.125,-2.512 -2.125,-2.512 -2.125,-2.662 -2.129,-2.681 -2.14,-2.697 -2.156,-2.708 -2.175,-2.712 -2.175,-2.712 -2.4,-2.712 -2.419,-2.716 -2.435,-2.727 -2.446,-2.743 -2.45,-2.762 -2.45,-2.762 -2.45,-2.912 -2.443,-2.937 -2.425,-2.955 -2.4,-2.962 -2.4,-2.962 -2.175,-2.962 -2.156,-2.966 -2.14,-2.977 -2.129,-2.993 -2.125,-3.012 -2.125,-3.012 -2.125,-3.166 -2.118,-3.191 -2.1,-3.209 -2.075,-3.216 -2.075,-3.216 -1.8,-3.216 -1.781,-3.212 -1.765,-3.201 -1.754,-3.185 -1.75,-3.166 -1.75,-3.166 -1.75,0.492 -1.754,0.511 -1.765,0.527 -1.781,0.538 -1.8,0.542 -1.8,0.542
  Top Layer region: 2.075,0.542 2.094,0.538 2.11,0.527 2.121,0.511 2.125,0.492 2.125,0.492 2.125,0.338 2.129,0.319 2.14,0.303 2.156,0.292 2.175,0.288 2.175,0.288 2.4,0.288 2.419,0.284 2.435,0.273 2.446,0.257 2.45,0.238 2.45,0.238 2.45,0.088 2.443,0.063 2.425,0.045 2.4,0.038 2.4,0.038 2.175,0.038 2.156,0.034 2.14,0.023 2.129,0.007 2.125,-0.012 2.125,-0.012 2.125,-0.162 2.132,-0.187 2.15,-0.205 2.175,-0.212 2.175,-0.212 2.4,-0.212 2.425,-0.219 2.443,-0.237 2.45,-0.262 2.45,-0.262 2.45,-0.412 2.446,-0.431 2.435,-0.447 2.419,-0.458 2.4,-0.462 2.4,-0.462 2.175,-0.462 2.156,-0.466 2.14,-0.477 2.129,-0.493 2.125,-0.512 2.125,-0.512 2.125,-0.662 2.129,-0.681 2.14,-0.697 2.156,-0.708 2.175,-0.712 2.175,-0.712 2.4,-0.712 2.419,-0.716 2.435,-0.727 2.446,-0.743 2.45,-0.762 2.45,-0.762 2.45,-0.912 2.446,-0.931 2.435,-0.947 2.419,-0.958 2.4,-0.962 2.4,-0.962 2.175,-0.962 2.156,-0.966 2.14,-0.977 2.129,-0.993 2.125,-1.012 2.125,-1.012 2.125,-1.162 2.129,-1.181 2.14,-1.197 2.156,-1.208 2.175,-1.212 2.175,-1.212 2.4,-1.212 2.419,-1.216 2.435,-1.227 2.446,-1.243 2.45,-1.262 2.45,-1.262 2.45,-1.412 2.446,-1.431 2.435,-1.447 2.419,-1.458 2.4,-1.462 2.4,-1.462 2.175,-1.462 2.156,-1.466 2.14,-1.477 2.129,-1.493 2.125,-1.512 2.125,-1.512 2.125,-1.662 2.129,-1.681 2.14,-1.697 2.156,-1.708 2.175,-1.712 2.175,-1.712 2.4,-1.712 2.419,-1.716 2.435,-1.727 2.446,-1.743 2.45,-1.762 2.45,-1.762 2.45,-1.912 2.446,-1.931 2.435,-1.947 2.419,-1.958 2.4,-1.962 2.4,-1.962 2.175,-1.962 2.156,-1.966 2.14,-1.977 2.129,-1.993 2.125,-2.012 2.125,-2.012 2.125,-2.162 2.129,-2.181 2.14,-2.197 2.156,-2.208 2.175,-2.212 2.175,-2.212 2.4,-2.212 2.419,-2.216 2.435,-2.227 2.446,-2.243 2.45,-2.262 2.45,-2.262 2.45,-2.412 2.446,-2.431 2.435,-2.447 2.419,-2.458 2.4,-2.462 2.4,-2.462 2.175,-2.462 2.156,-2.466 2.14,-2.477 2.129,-2.493 2.125,-2.512 2.125,-2.512 2.125,-2.662 2.129,-2.681 2.14,-2.697 2.156,-2.708 2.175,-2.712 2.175,-2.712 2.4,-2.712 2.419,-2.716 2.435,-2.727 2.446,-2.743 2.45,-2.762 2.45,-2.762 2.45,-2.912 2.446,-2.931 2.435,-2.947 2.419,-2.958 2.4,-2.962 2.4,-2.962 2.175,-2.962 2.156,-2.966 2.14,-2.977 2.129,-2.993 2.125,-3.012 2.125,-3.012 2.125,-3.166 2.121,-3.185 2.11,-3.201 2.094,-3.212 2.075,-3.216 2.075,-3.216 1.8,-3.216 1.775,-3.209 1.757,-3.191 1.75,-3.166 1.75,-3.166 1.75,0.492 1.754,0.511 1.765,0.527 1.781,0.538 1.8,0.542 1.8,0.542
  silkscreen extent -3.12,-3.88 2.63,3.88, body extent -2.25,-3.5 2.25,3.5, height 0.85
WEEE_Minimum [mil] "WEEElie bin"
  silkscreen extent -95,-172 99,104
Wurth_691236510002 [mm] "Terminal Block, 5.08mm, 2x1, R/A, TH"
  rrect50% 2.25x2.25 hole 1.5: 1(-2.54,0)
  round 2.25 hole 1.5: 2(2.54,0)
  body extent -5.68,-5.5 5.08,5.85, height 18

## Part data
BODE SYNC: library part CMP-0055139-2, "Test Point, Miniature, White, TH", Color=White, Manufacturer="Keystone Electronics", PartNumber=5002, Supplier Part Number 1=36-5002-ND
C1: library part CMP-0120543-1, "Conductive Polymer Hybrid Aluminum Electrolytic Capacitors 47uF ±20% 80V RADIAL SMT 10x10.2mm", Leakage Current=37.6uA, Manufacturer=Panasonic, Operating Temperature Range="-55°C to +105°C", Tolerance_%=20%, ValueDisplayed=47uF
C2 C3 C7 C8 C9: library part CMP-0084773-1, "CAP, CERM, 0.01 µF, 100 V,+/- 10%, X7R, AEC-Q200 Grade 1, 0603", Cap_Case=0603, Manufacturer=MuRata, TempCo=X7R, Tolerance_%=10%, Value2=100V, ValueDisplayed=0.01µF
C4: library part CMP-0008790-2, "CAP, CERM, 2.2 uF, 100 V, +/- 10%, X7S, AEC-Q200 Grade 1, 1206", Cap_Case=1206_180, Manufacturer=TDK, Supplier Part Number 1=445-6994-1-ND, TempCo=X7S, Tolerance_%=10%, Value1="0.005718 ohm", Value2=100V, ValueDisplayed=2.2uF
C5: library part CMP-0009134-2, "CAP, CERM, 4.7 uF, 100 V, +/- 10%, X7S, 1210", Cap_Case=1210_220, Manufacturer=TDK, Supplier Part Number 1=445-6042-1-ND, TempCo=X7S, Tolerance_%=10%, Value1="0.004236 ohm", Value2=100V, ValueDisplayed=4.7uF
C6: library part CMP-0009150-2, "CAP, CERM, 4.7 uF, 100 V, +/- 10%, X7S, AEC-Q200 Grade 1, 1210", Cap_Case=1210_220, Manufacturer=TDK, Supplier Part Number 1=445-7005-1-ND, TempCo=X7S, Tolerance_%=10%, Value1="0.004236 ohm", Value2=100V, ValueDisplayed=4.7uF
C10 C11: library part CMP-0861070-1, "CAP, CERM, 1 µF, 100 V,+/- 10%, X7R, AEC-Q200 Grade 1, 0805", Cap_Case=0805, Manufacturer=AVX, TempCo=X7R, Tolerance_%=10%, Value2=100V, ValueDisplayed=1µF
C12 C13 C14 C15 C16: library part CMP-0064935-4, "CAP, CERM, 0.1 uF, 100 V,+/- 10%, X7R, AEC-Q200 Grade 1, 0603", Cap_Case=0603, Manufacturer=MuRata, Supplier Part Number 1=490-13420-1-ND, TempCo=X7R, Tolerance_%=10%, Value1=Unknown, Value2=100V, ValueDisplayed=0.1uF
C17 C18 C19 C20: library part CMP-0093675-1, "4.7uF ±10% 100V Ceramic Capacitor X7S 1210 (3225 Metric)", Manufacturer=Murata, Operating Temperature Range="-55°C to +125°C", TempCo=22%, Temperature Characteristic=X7S, Tolerance_%=10%, ValueDisplayed=4.7uF
C21 C22 C23: library part CMP-0093675-1, "4.7uF ±10% 100V Ceramic Capacitor X7S 1210 (3225 Metric)", Manufacturer=Murata, Operating Temperature Range="-55°C to +125°C", Part Number=GCJ32DC72A475KE01L, TempCo=22%, Temperature Characteristic=X7S, Tolerance_%=10%, ValueDisplayed=4.7uF
C24 C25 C26 C27 C28 C29 C30 C31 C32 C33: library part CMP-0006333-2, "CAP, CERM, 0.01 uF, 100 V, +/- 10%, X7S, AEC-Q200 Grade 1, 0402", Cap_Case=0402, Manufacturer=TDK, Supplier Part Number 1=445-6910-1-ND, TempCo=X7S, Tolerance_%=10%, Value1="0.410191 ohm", Value2=100V, ValueDisplayed=0.01uF
C34 C35: library part CMP-0006302-2, "CAP, CERM, 2.2 uF, 10 V, +/- 10%, X7S, 0402", Cap_Case=0402_065, Manufacturer=TDK, Supplier Part Number 1=445-9097-1-ND, TempCo=X7S, Tolerance_%=10%, Value1="0.005925 ohm", Value2=10V, ValueDisplayed=2.2uF
C36 C37 C39: library part CMP-0080702-1, "CAP, CERM, 0.1 µF, 16 V,+/- 5%, X7R, AEC-Q200 Grade 1, 0402", Cap_Case=0402, Manufacturer=MuRata, Supplier Part Number 1=490-16433-1-ND, TempCo=X7R, Tolerance_%=5%, Value2=16V, ValueDisplayed=0.1µF
C38: library part CMP-0750097-1, "CAP, CERM, 0.47 µF, 100 V,+/- 10%, X7R, 0805", Cap_Case=0805, Manufacturer=AVX, TempCo=X7R, Tolerance_%=10%, Value2=100V, ValueDisplayed=0.47µF
C40: library part CMP-0006674-2, "CAP, CERM, 0.01 uF, 50 V, +/- 10%, X7R, 0402", Cap_Case=0402, Manufacturer=MuRata, Supplier Part Number 1=490-4516-1-ND, TempCo=X7R, Tolerance_%=10%, Value1=Unknown, Value2=50V, ValueDisplayed=0.01uF
C41 C52: library part CMP-0064916-2, "CAP, CERM, 10 pF, 50 V,+/- 1%, C0G/NP0, 0402", Cap_Case=0402, Manufacturer=MuRata, Supplier Part Number 1=490-6186-1-ND, TempCo=C0G/NP0, Tolerance_%=1%, Value1=Unknown, Value2=50V, ValueDisplayed=10pF
C42: library part CMP-0079150-1, "CAP, CERM, 0.1 µF, 10 V,+/- 10%, X7R, AEC-Q200 Grade 1, 0402", Cap_Case=0402, Manufacturer=Kemet, Supplier Part Number 1=399-15984-1-ND, TempCo=X7R, Tolerance_%=10%, Value2=10V, ValueDisplayed=0.1µF
C43: library part CMP-0007058-4, "CAP, CERM, 4.7 uF, 10 V, +/- 10%, X7S, 0603", Cap_Case=0603, Manufacturer=TDK, Supplier Part Number 1=445-14258-1-ND, TempCo=X7S, Tolerance_%=10%, Value1=Unknown, Value2=10V, ValueDisplayed=4.7uF
C44 C45: library part CMP-0012660-3, "CAP, Tantalum Polymer, 150 uF, 16 V, +/- 20%, 0.065 ohm, AEC-Q200 Grade 1, 7343-31 SMD", Cap_Case=7343-31, Manufacturer=Kemet, Supplier Part Number 1=399-12105-1-ND, Tolerance_%=20%, Value1="0.05 ohm", Value2=16V, ValueDisplayed=150uF
C46 C47: library part CMP-0750160-1, "CAP, CERM, 330 pF, 100 V,+/- 5%, C0G/NP0, 0402", Cap_Case=0402, Manufacturer=TDK, TempCo=C0G/NP0, Tolerance_%=5%, Value2=100V
C48 C53 C63 C64: library part CMP-0080610-1, "CAP, CERM, 0.1 µF, 25 V,+/- 10%, X7R, AEC-Q200 Grade 1, 0402", Cap_Case=0402, Manufacturer=TDK, Supplier Part Number 1=445-6902-1-ND, TempCo=X7R, Tolerance_%=10%, Value2=25V, ValueDisplayed=0.1µF
C49 C61: library part CMP-0080552-1, "CAP, CERM, 22 µF, 25 V,+/- 10%, X7R, AEC-Q200 Grade 1, 1210", Cap_Case=1210, Manufacturer="Taiyo Yuden", PartNumber=TMK325B7226KMHP, Supplier Part Number 1=587-5949-1-ND, TempCo=X7R, Tolerance_%=10%, Value2=25V, ValueDisplayed=22µF
C50 C51 C62: library part CMP-0080552-1, "CAP, CERM, 22 µF, 25 V,+/- 10%, X7R, AEC-Q200 Grade 1, 1210", Cap_Case=1210, Manufacturer="Taiyo Yuden", Supplier Part Number 1=587-5949-1-ND, TempCo=X7R, Tolerance_%=10%, Value2=25V, ValueDisplayed=22µF
C54: library part CMP-0006306-2, "CAP, CERM, 0.033 uF, 25 V, +/- 10%, X7R, AEC-Q200 Grade 1, 0402", Cap_Case=0402, Manufacturer=TDK, Supplier Part Number 1=445-12247-1-ND, TempCo=X7R, Tolerance_%=10%, Value1=Unknown, Value2=25V, ValueDisplayed=0.033uF
C55: library part CMP-0064916-2, "CAP, CERM, 10 pF, 50 V,+/- 1%, C0G/NP0, 0402", Cap_Case=0402, Manufacturer=MuRata, Supplier Part Number 1=490-6186-1-ND, TempCo=C0G/NP0, Tolerance_%=1%, Value1=Unknown, Value2=50V, ValueDisplayed=DNP
C56: library part CMP-0086096-1, "CAP, CERM, 680 pF, 50 V,+/- 1%, C0G/NP0, AEC-Q200 Grade 1, 0402", Cap_Case=0402, Manufacturer=MuRata, TempCo=C0G/NP0, Tolerance_%=1%, Value2=50V, ValueDisplayed=680pF
C57: library part CMP-0006670-2, "CAP, CERM, 5600 pF, 25 V, +/- 10%, X7R, 0402", Cap_Case=0402, Manufacturer=MuRata, Supplier Part Number 1=490-5420-1-ND, TempCo=X7R, Tolerance_%=10%, Value1=Unknown, Value2=25V, ValueDisplayed=5600pF
C58: library part CMP-0006705-2, "CAP, CERM, 270 pF, 100 V, +/- 10%, X7R, 0402", Cap_Case=0402, Manufacturer=MuRata, Supplier Part Number 1=GRM155R72A271KA01D-ND, TempCo=X7R, Tolerance_%=10%, Value1=Unknown, Value2=100V, ValueDisplayed=270pF
C59 C60: library part CMP-0012660-3, "CAP, Tantalum Polymer, 150 uF, 16 V, +/- 20%, 0.065 ohm, AEC-Q200 Grade 1, 7343-31 SMD", Cap_Case=7343-31, Manufacturer=Kemet, PartNumber=T598D157M016ATE065, Supplier Part Number 1=399-12105-1-ND, Tolerance_%=20%, Value1="0.05 ohm", Value2=16V, ValueDisplayed=150uF
D1: library part CMP-0121148-1, "Diode Schottky 100 V 2A Surface Mount"
GND GND_Main TP7: library part CMP-0055148-1, "Test Point, Multipurpose, Black, TH", Color=Black, Manufacturer=Keystone, PartNumber=5011, Supplier Part Number 1=36-5011-ND
GND VOUT: library part CMP-0055442-1, "Terminal 50A Lug", Manufacturer=Panduit, PartNumber=CB35-36-CY, Supplier Part Number 1=CB35-36-CY-ND, Voltage_V=600V
J1: library part CMP-0079044-1, "Terminal Block, 5.08mm, 2x1, R/A, TH", Color=Green, Current_A=20A, Manufacturer="Wurth Elektronik", Supplier Part Number 1=732-10995-ND, Voltage_V=300V
L1: library part CMP-0120047-1, "1.2 µH Shielded Molded Inductor 20.1 A 4.6mOhm Max Nonstandard", Digikey Part Number=2457-XGL5050-122MEC-ND, Manufacturer=Coilcraft, Operating Temperature Range=to, Self Resonant Frequency=50MHz, Test Frequency=1MHz, Tolerance_%=20%
L2: library part CMP-0084691-1, "Coupled inductor,  ohm, AEC-Q200 Grade 1, SMD", Manufacturer=TDK, PartNumber=ACM12V-701-2PL-TL00
L3: library part CMP-0120649-1, "Shielded Power Inductors 4.7µH ±20%", Manufacturer=Coilcraft, Operating Temperature Range=to, Self Resonant Frequency=15MHz, Test Frequency=100kHz, Tolerance_%=20%
Logo2 Logo?: library part CMP-0074837-2, "IEC 61010-1 Hot Surface Warning", Manufacturer="Texas Instruments"
LOGO3: library part CMP-0074835-1, "IEC 61010-1 High Voltage Warning"
Logo4: library part CMP-0074769-1
NT1: library part CMP-0078142-3, "Single point connection between nets.", Manufacturer=N/A
R1: library part CMP-0016193-2, "RES, 1.0, 5%, 1 W, 2010", Manufacturer=Bourns, Power_W=1W, Supplier Part Number 1=652-CRM2010JW1R0ELF, TempCo="150 ppm/C", Tolerance_%=5%, Value_Code=1R00, ValueDisplayed=1.0
R2 R3 R6 R8 R14: library part CMP-0026822-3, "RES, 0, 5%, 0.063 W, AEC-Q200 Grade 0, 0402", Manufacturer=Vishay-Dale, Power_W=63mW, Supplier Part Number 1=541-0.0JCT-ND, TempCo="200 ppm/C", Tolerance_%=5%, Value2=0.063W, Value_Code=0000, ValueDisplayed=0
R4: library part CMP-0026401-2, "RES, 499 k, 1%, 0.063 W, AEC-Q200 Grade 0, 0402", Manufacturer=Vishay-Dale, Power_W=63mW, Supplier Part Number 1=541-499KLCT-ND, TempCo="100 ppm/C", Tolerance_%=1%, Value2=0.063W, Value_Code=499k
R5 R9: library part CMP-0025885-5, "RES, 0, 5%, 0.1 W, 0603", Manufacturer=Yageo, Power_W=100mW, Supplier Part Number 1=311-0.0GRCT-ND, TempCo="200 ppm/C", Tolerance_%=5%, Value2=0.1W, Value_Code=0000, ValueDisplayed=0
R7: library part CMP-0090631-1, "3 mOhms ±1% 1W Chip Resistor Wide 0805 (2012 Metric), 0508 Automotive AEC-Q200, Current Sense Metal Foil", Digikey Part Number=408-1593-1-ND, Manufacturer=Susumu, Mouser Part Number=754-KRL2012EMR003FT5, Operating Temperature Range="-55°C to +155°C", Power_W=1W, TempCo=50ppm/°C, Tolerance_%=1%
R10: library part CMP-0095678-1, "4 mOhms ±1% 1W Chip Resistor Wide 0805 (2012 Metric), 0508 Automotive AEC-Q200, Current Sense Metal Foil", Digikey Part Number=408-1594-1-ND, Manufacturer=Susumu, Mouser Part Number=754-KRL2012EMR004FT5, Operating Temperature Range="-55°C to +155°C", Power_W=1W, TempCo=50ppm/°C, Tolerance_%=1%
R11: library part CMP-0026067-3, "RES, 19.1 k, 1%, 0.063 W, AEC-Q200 Grade 0, 0402", Manufacturer=Vishay-Dale, Power_W=63mW, Supplier Part Number 1=541-19.1KLCT-ND, TempCo="100 ppm/C", Tolerance_%=1%, Value2=0.063W, Value_Code=19k1, ValueDisplayed=19.1k
R12 R19: library part CMP-0026753-1, "RES, 100 k, 1%, 0.063 W, AEC-Q200 Grade 0, 0402", Manufacturer="Stackpole Electronics Inc", PartNumber=RMCF0402FT100K, Power_W=63mW, Supplier Part Number 1=RMCF0402FT100KCT-ND, TempCo="100 ppm/C", Tolerance_%=1%, Value2=0.063W, Value_Code=100k
R13: library part CMP-0026404-2, "RES, 49.9, 1%, 0.063 W, AEC-Q200 Grade 0, 0402", Manufacturer=Vishay-Dale, Power_W=63mW, Supplier Part Number 1=541-49.9LCT-ND, TempCo="100 ppm/C", Tolerance_%=1%, Value2=0.063W, Value_Code=49R9, ValueDisplayed=49.9
R15: library part CMP-0018687-3, "RES, 47, 5%, 0.25 W, AEC-Q200 Grade 0, 1206", Manufacturer=Vishay-Dale, Power_W=250mW, Supplier Part Number 1=541-47ECT-ND, TempCo="200 ppm/C", Tolerance_%=5%, Value2=0.25W, Value_Code=47R0, ValueDisplayed=47
R16 R20: library part CMP-0081856-1, "RES, 0, 0%, 0.2 W, AEC-Q200 Grade 0, 0402", Manufacturer=Vishay-Dale, PartNumber=CRCW04020000Z0EDHP, Power_W=200mW, Supplier Part Number 1=541-0.0YBTR-ND, Tolerance_%=0%, Value2=0.2W, Value_Code=0
R17: library part CMP-0022448-4, "RES, 49.9, 1%, 0.1 W, AEC-Q200 Grade 0, 0603", Manufacturer=Vishay-Dale, Power_W=100mW, Supplier Part Number 1=541-49.9HCT-ND, TempCo="100 ppm/C", Tolerance_%=1%, Value2=0.1W, Value_Code=49R9, ValueDisplayed=49.9
R18: library part CMP-0026539-2, "RES, 73.2 k, 1%, 0.063 W, AEC-Q200 Grade 0, 0402", Manufacturer=Vishay-Dale, Power_W=63mW, Supplier Part Number 1=541-73.2KLCT-ND, TempCo="100 ppm/C", Tolerance_%=1%, Value2=0.063W, Value_Code=73k2, ValueDisplayed=73.2k
R21: library part CMP-0026822-3, "RES, 0, 5%, 0.063 W, AEC-Q200 Grade 0, 0402", Manufacturer="Stackpole Electronics Inc", Power_W=63mW, Supplier Part Number 1=RMCF0402FT100KCT-ND, TempCo="100 ppm/C", Tolerance_%=1%, Value2=0.063W, Value_Code=100k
